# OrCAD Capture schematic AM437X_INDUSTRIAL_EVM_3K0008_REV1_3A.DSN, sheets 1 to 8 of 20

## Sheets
1 Pg15: Motor Sense: size C; title: AM437x Industrial EVM; rev: 1.3A; company: Texas Instruments; note: am437x_industrial_evm_3k0008.dsn; note: ARM MPU BU; note: Final
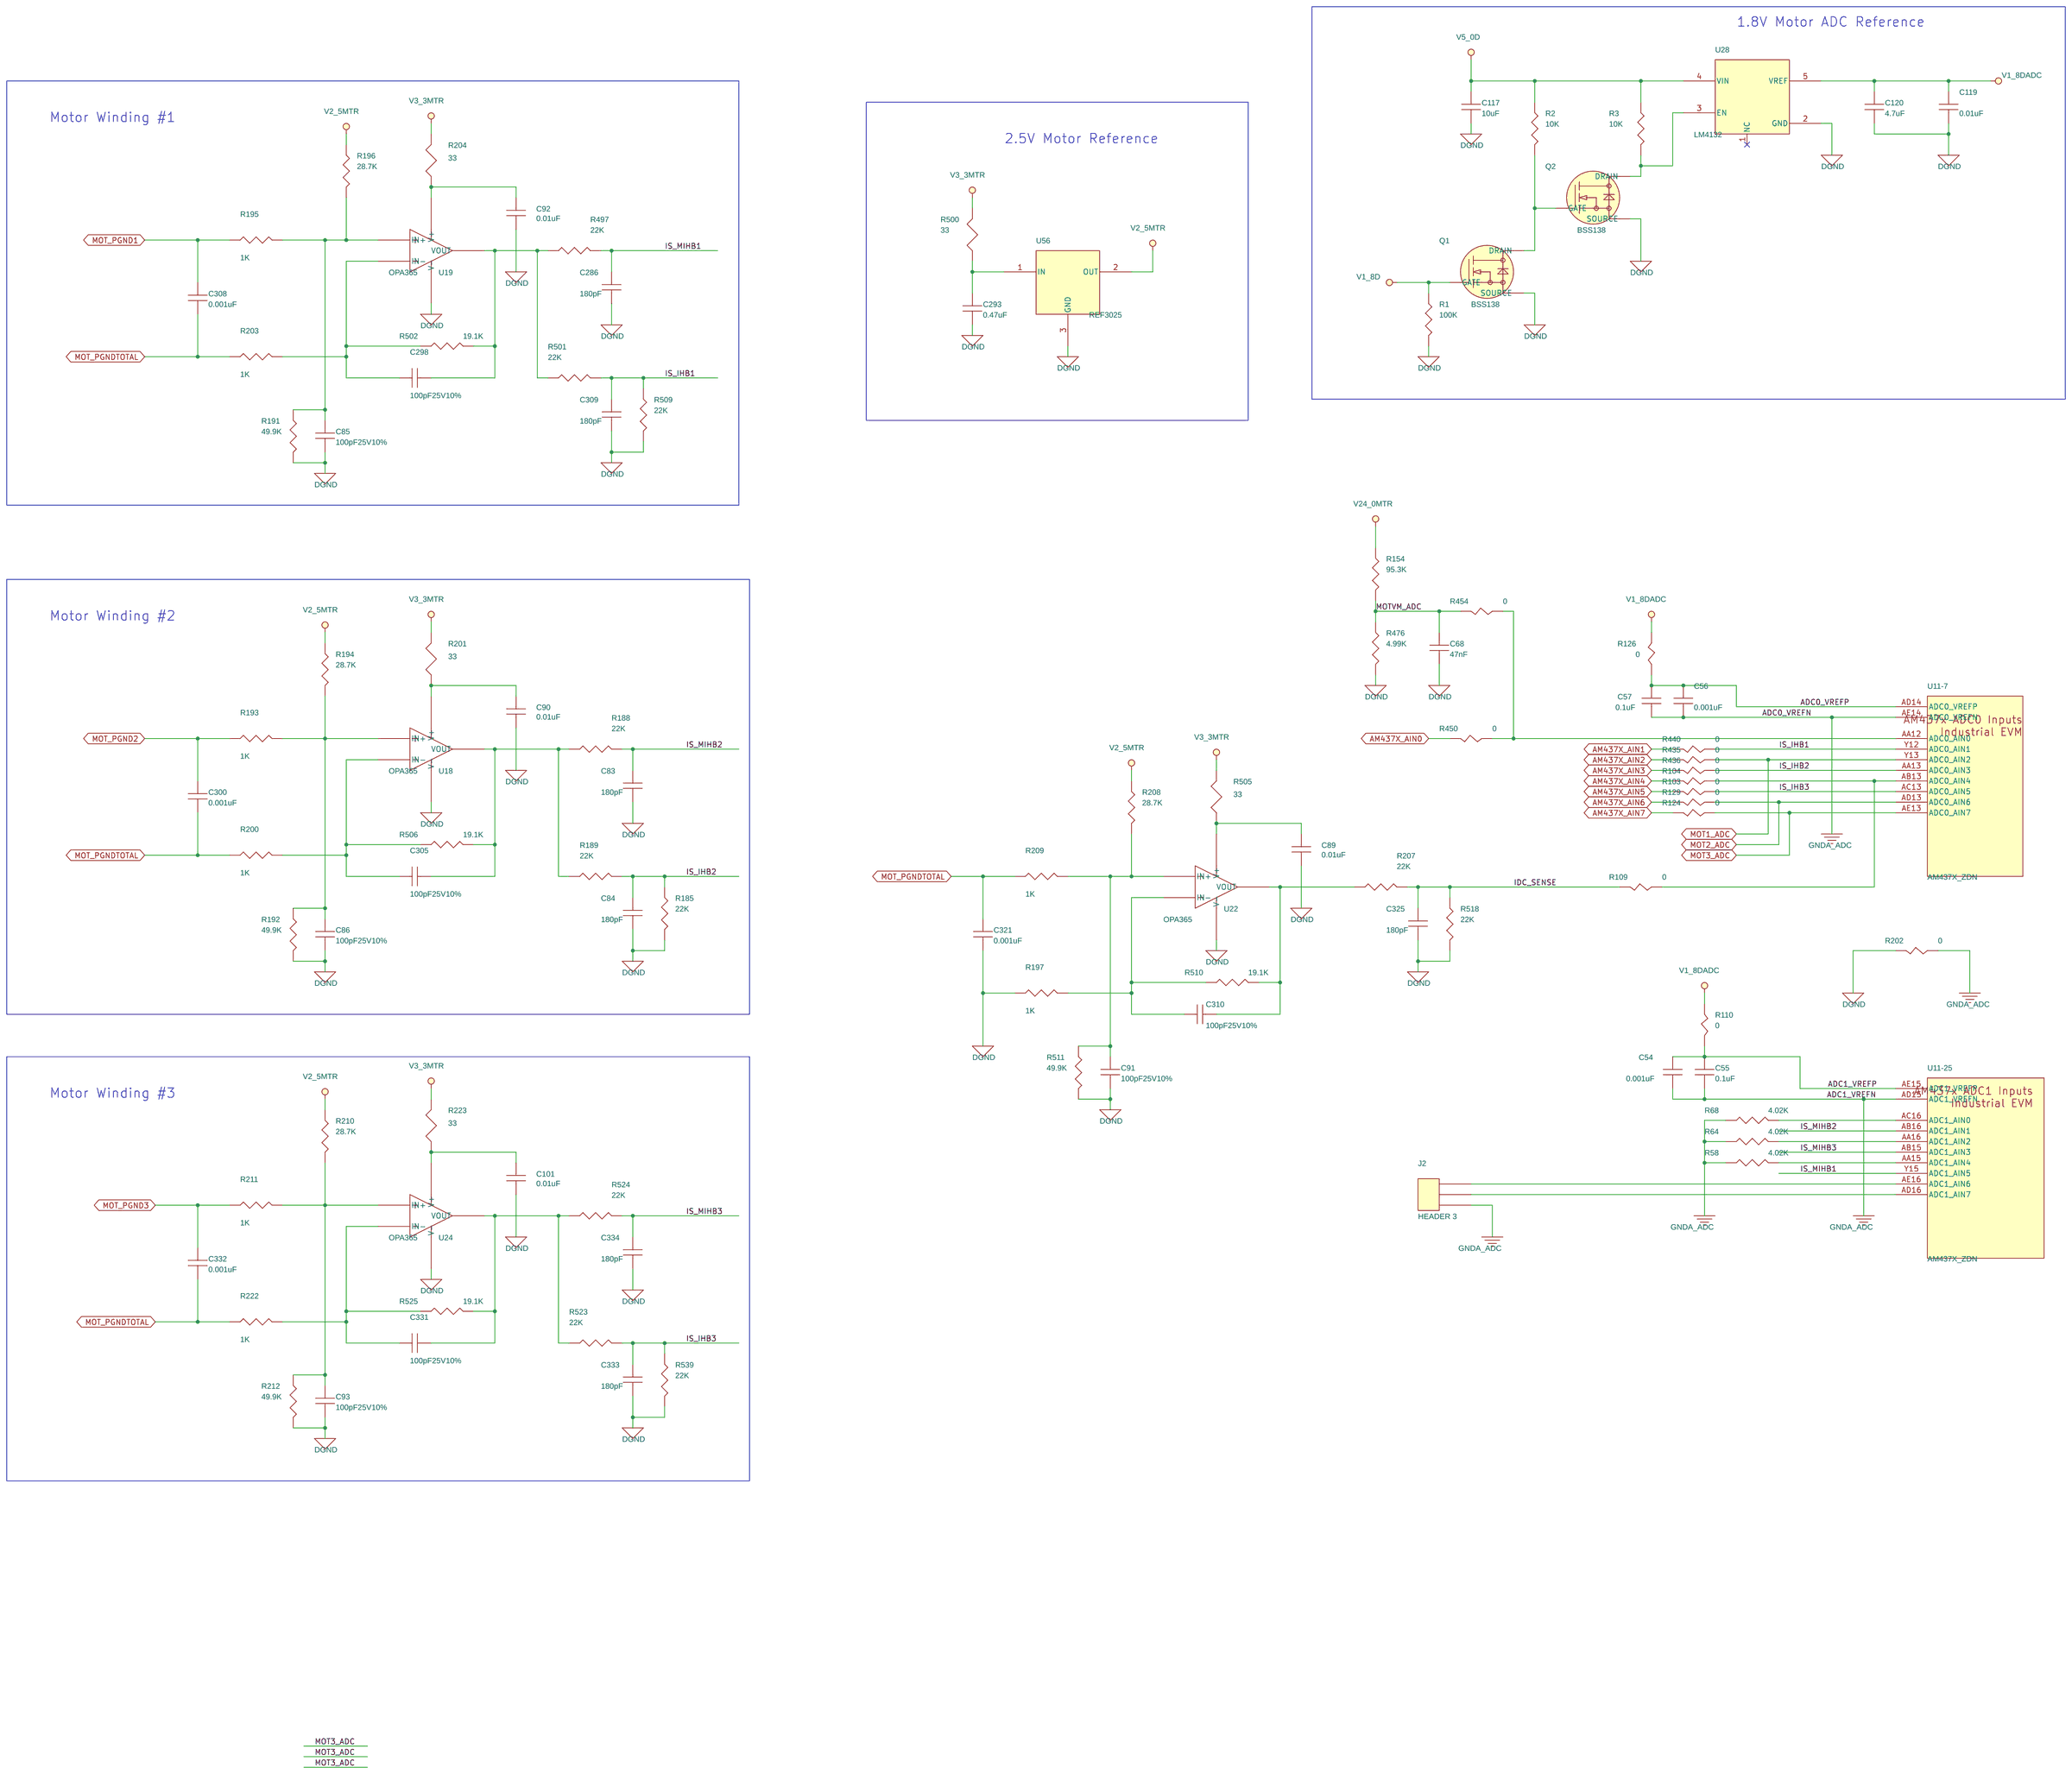
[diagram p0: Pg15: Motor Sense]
2 Pg12: Camera #0: size C
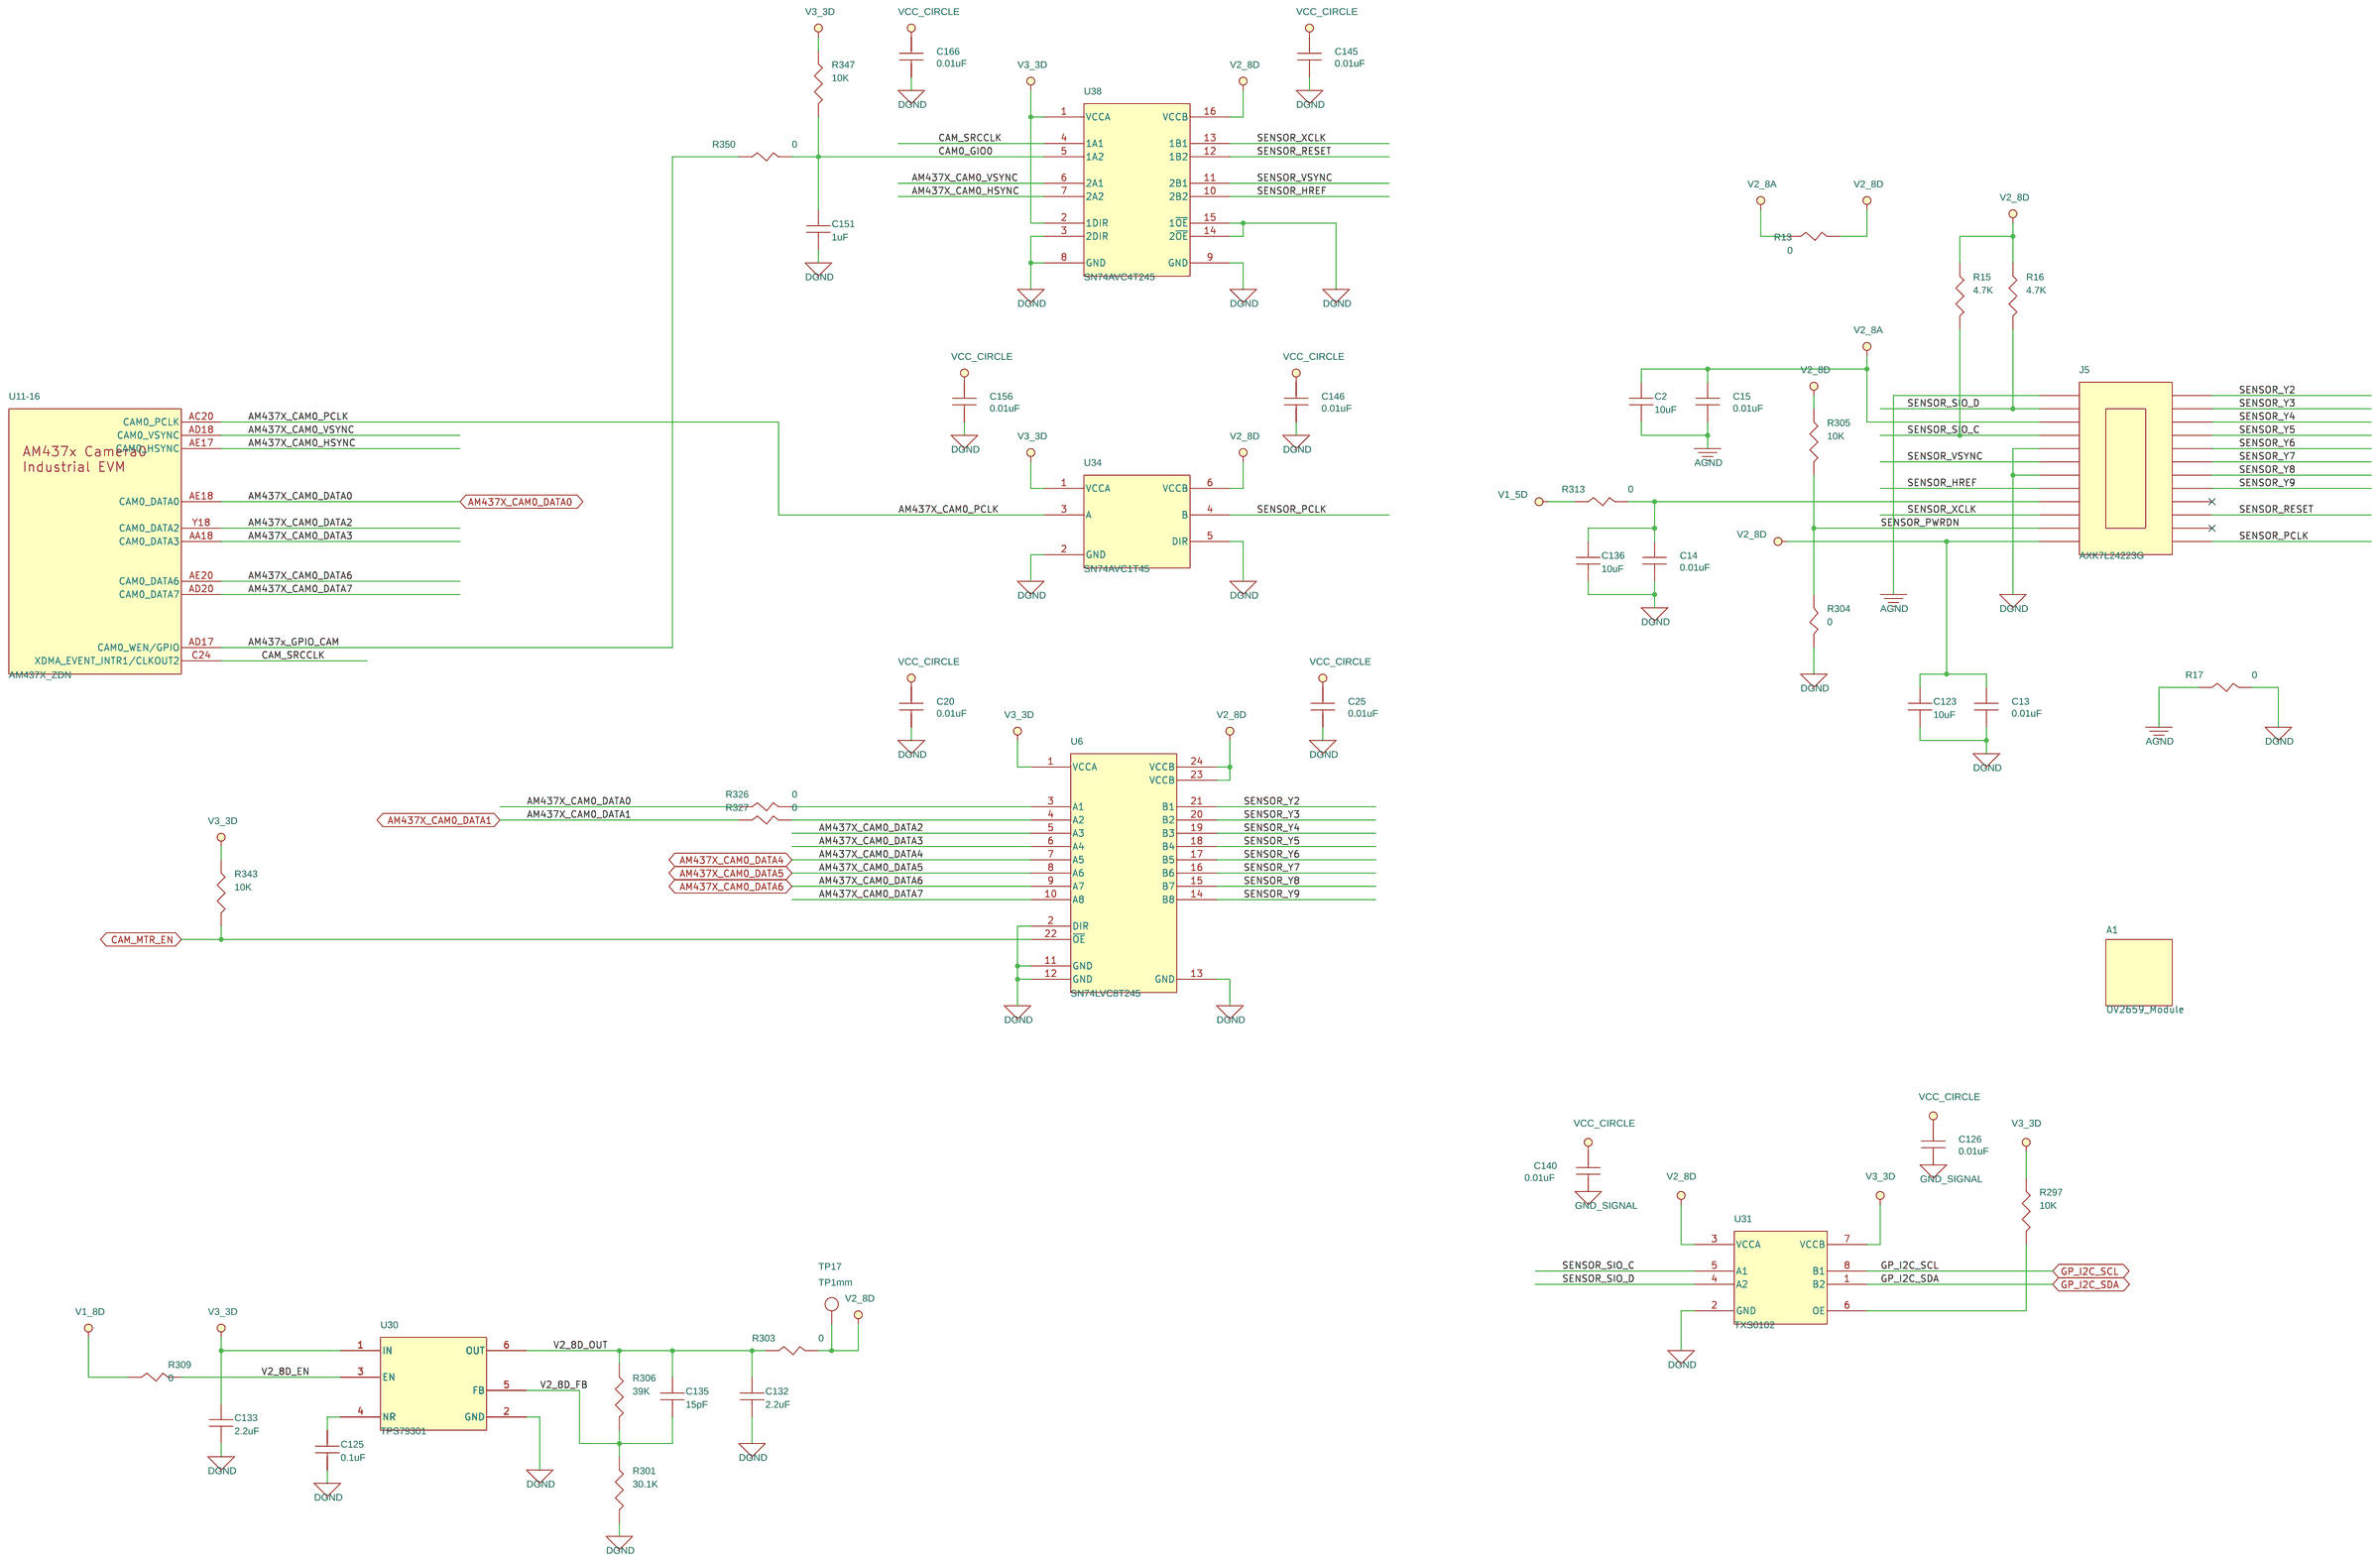
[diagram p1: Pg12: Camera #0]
3 Pg09: EtherCAT: size C
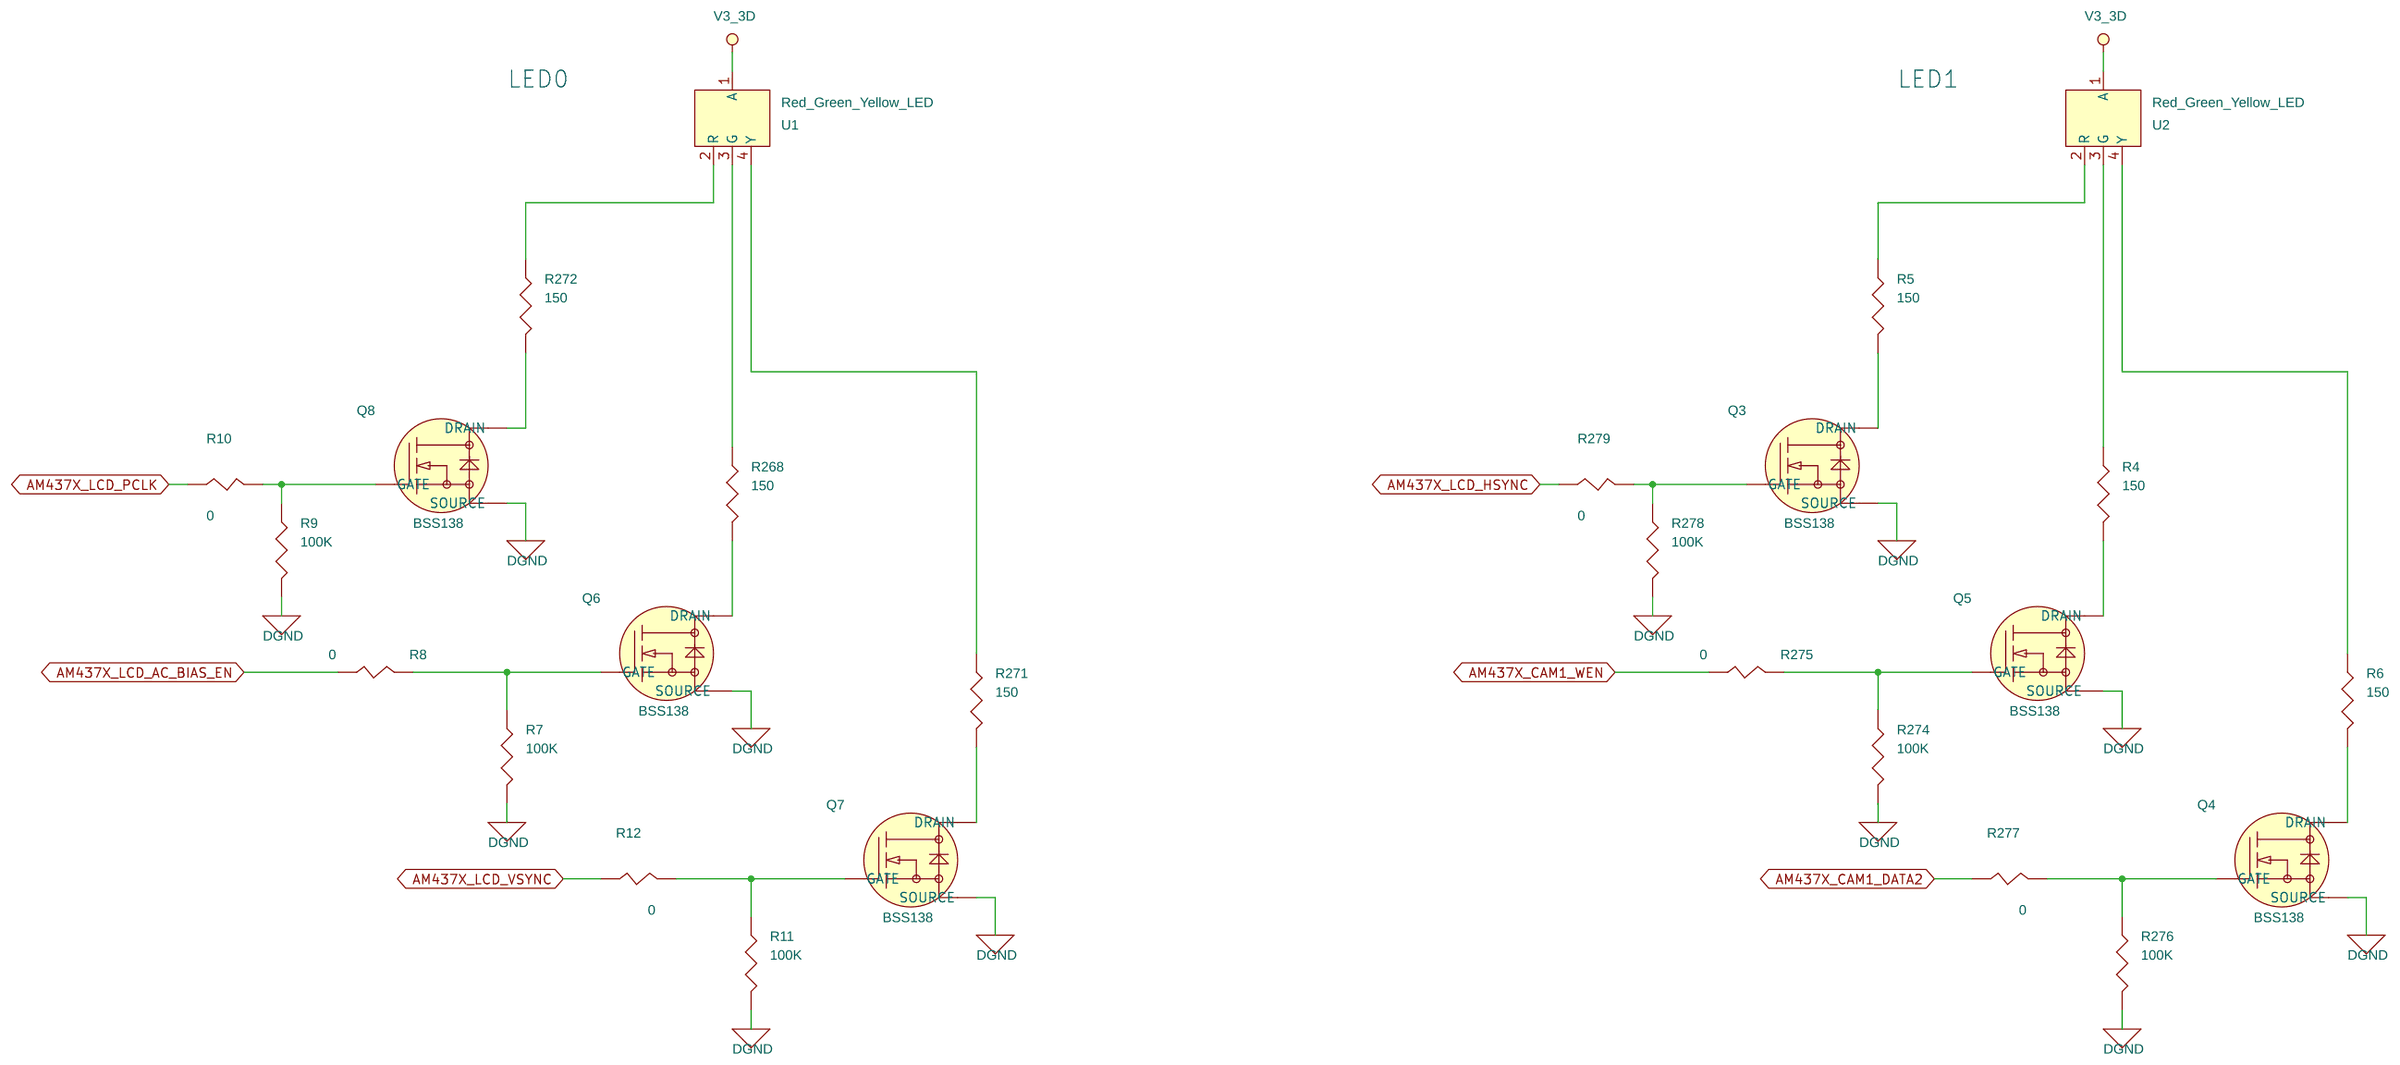
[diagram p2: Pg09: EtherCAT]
4 Pg20: RTC: size C
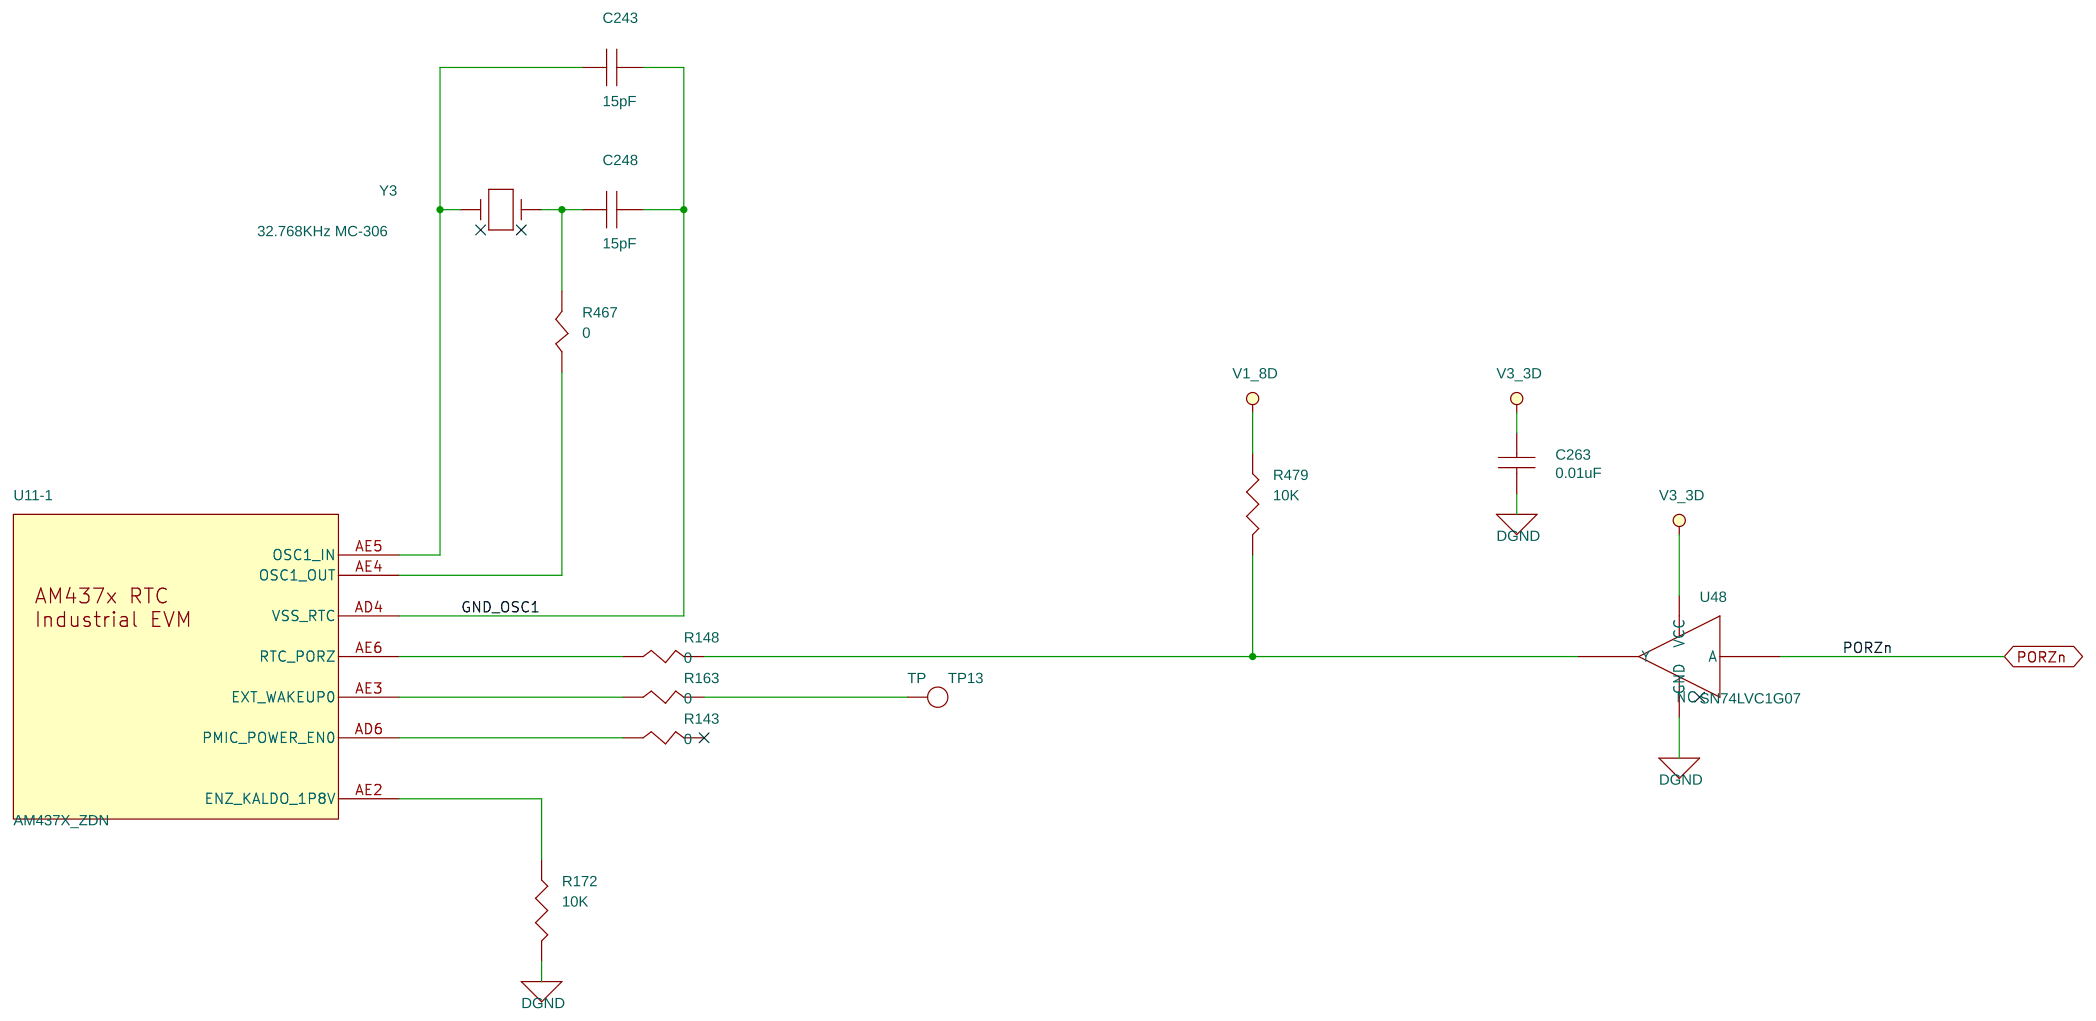
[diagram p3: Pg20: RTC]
5 Pg18: USB JTAG: size C
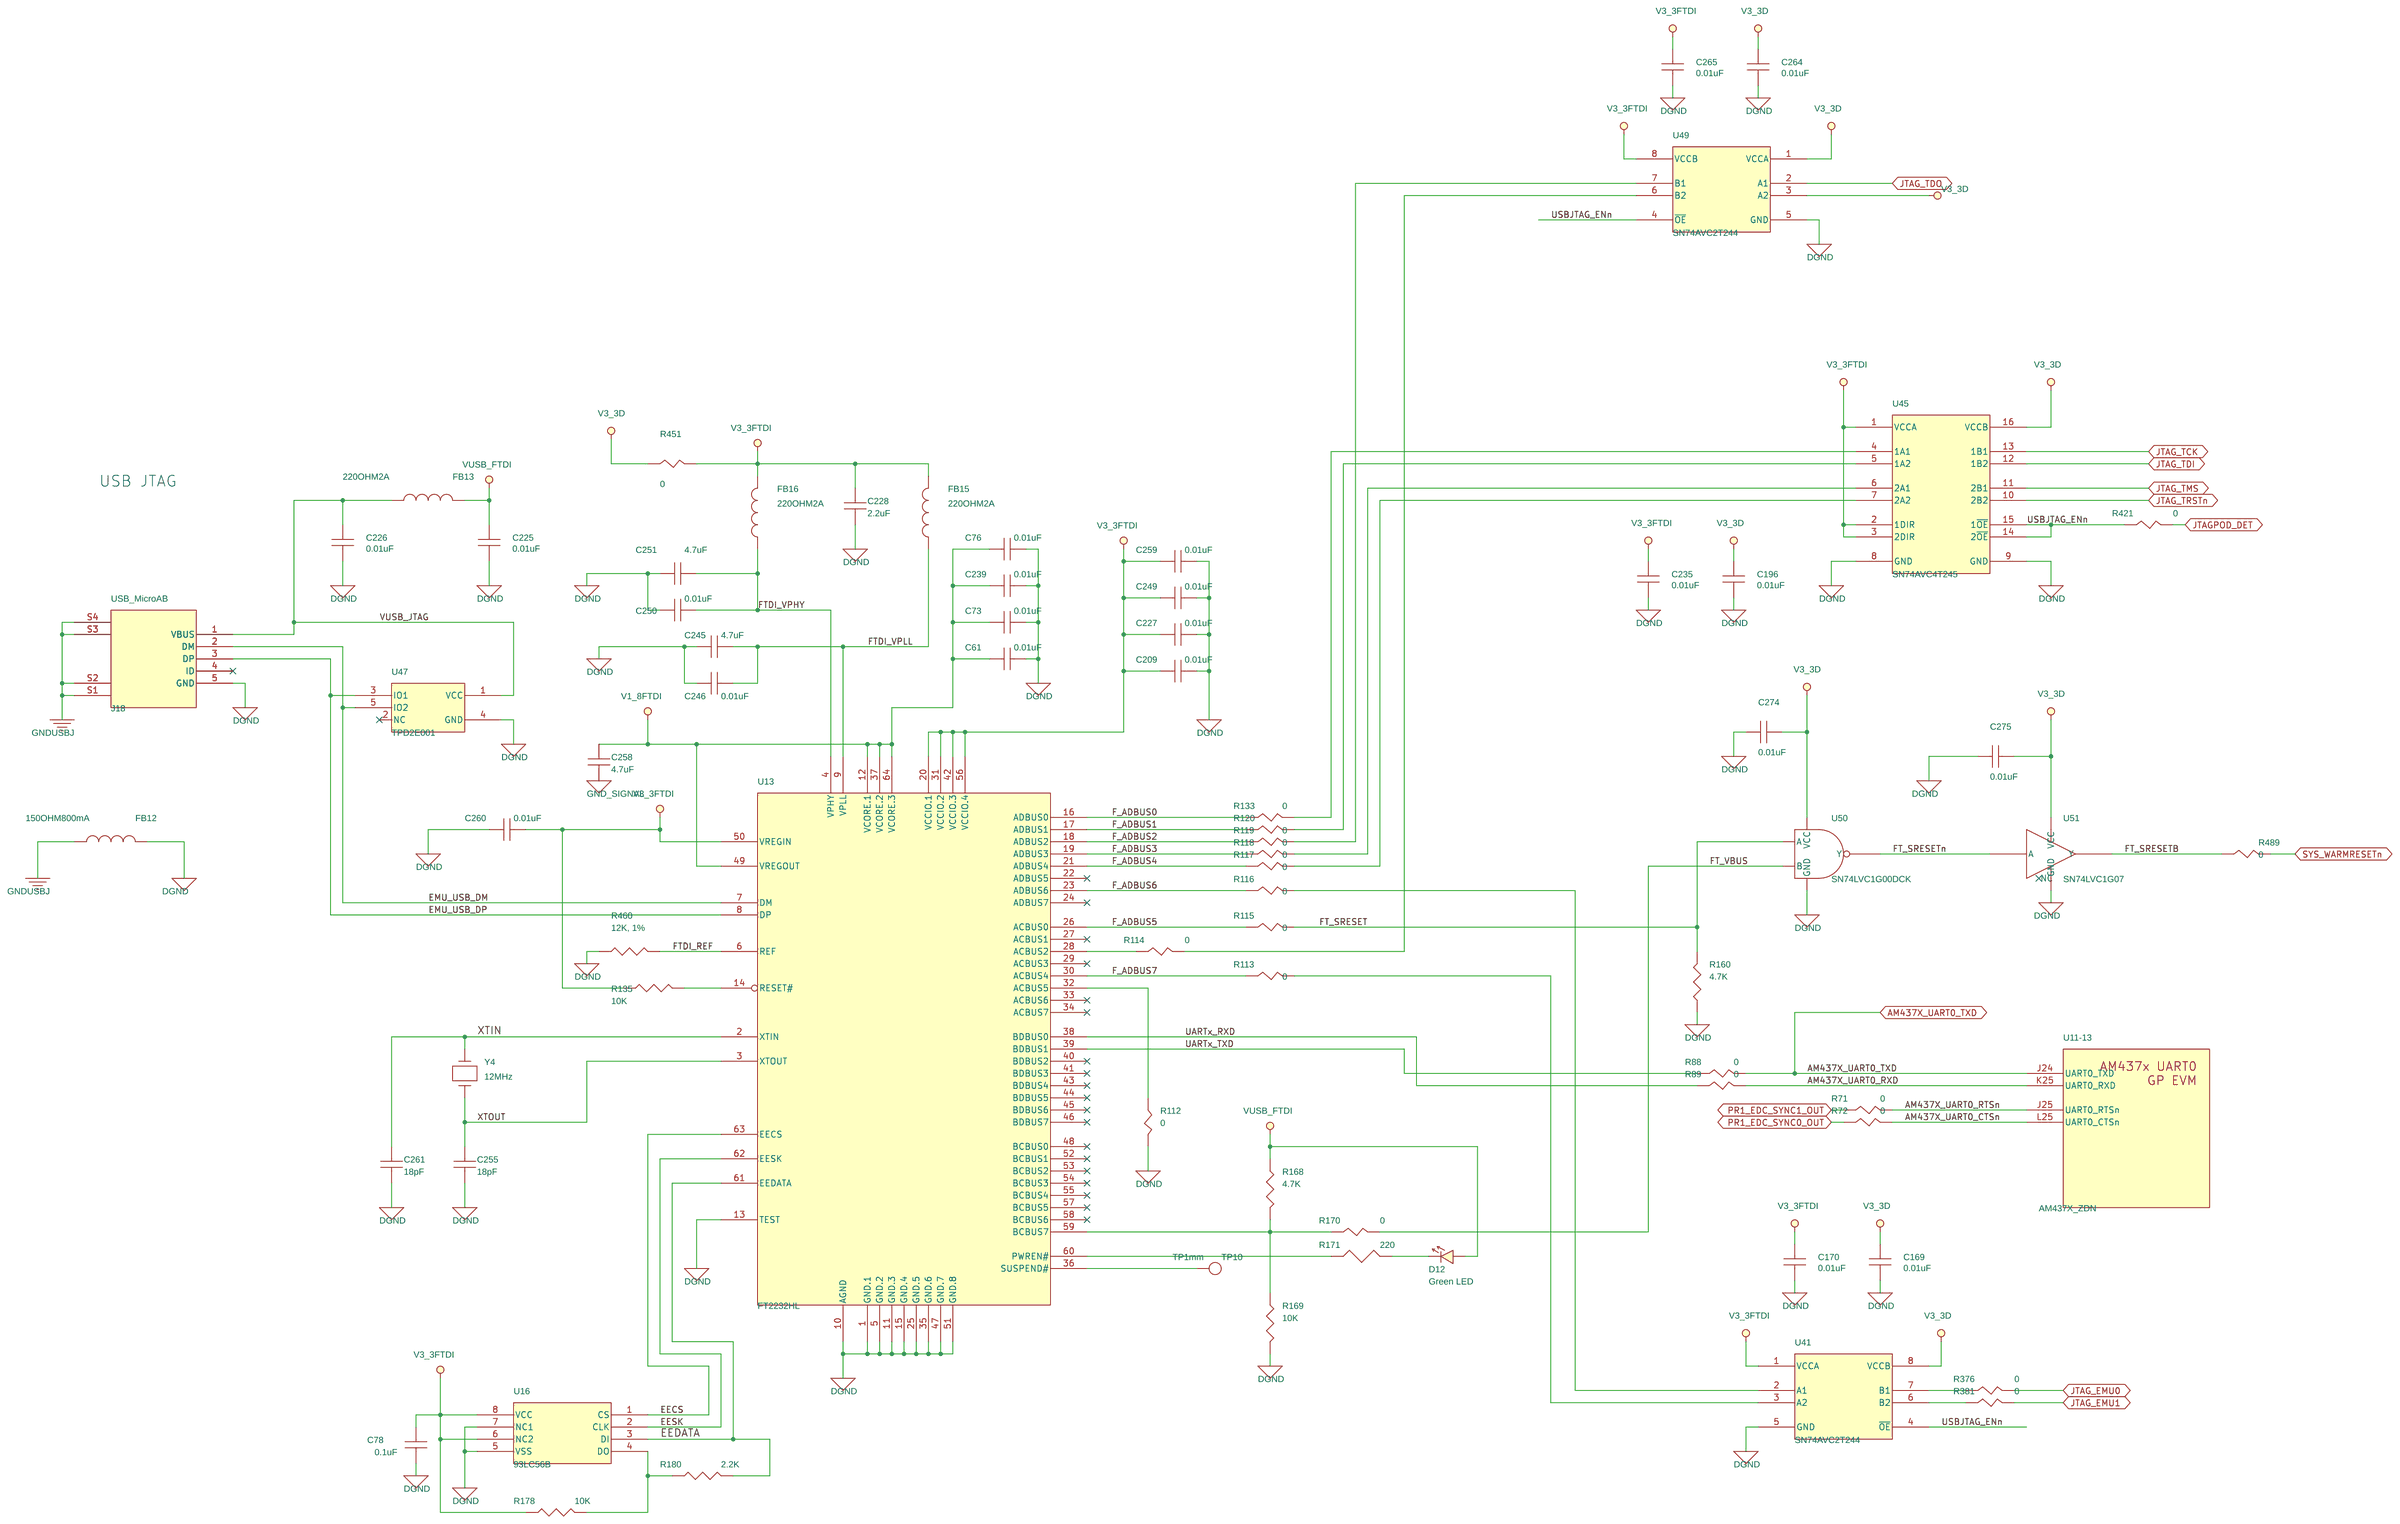
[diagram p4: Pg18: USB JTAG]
6 Pg17: JTAG Debug: size C
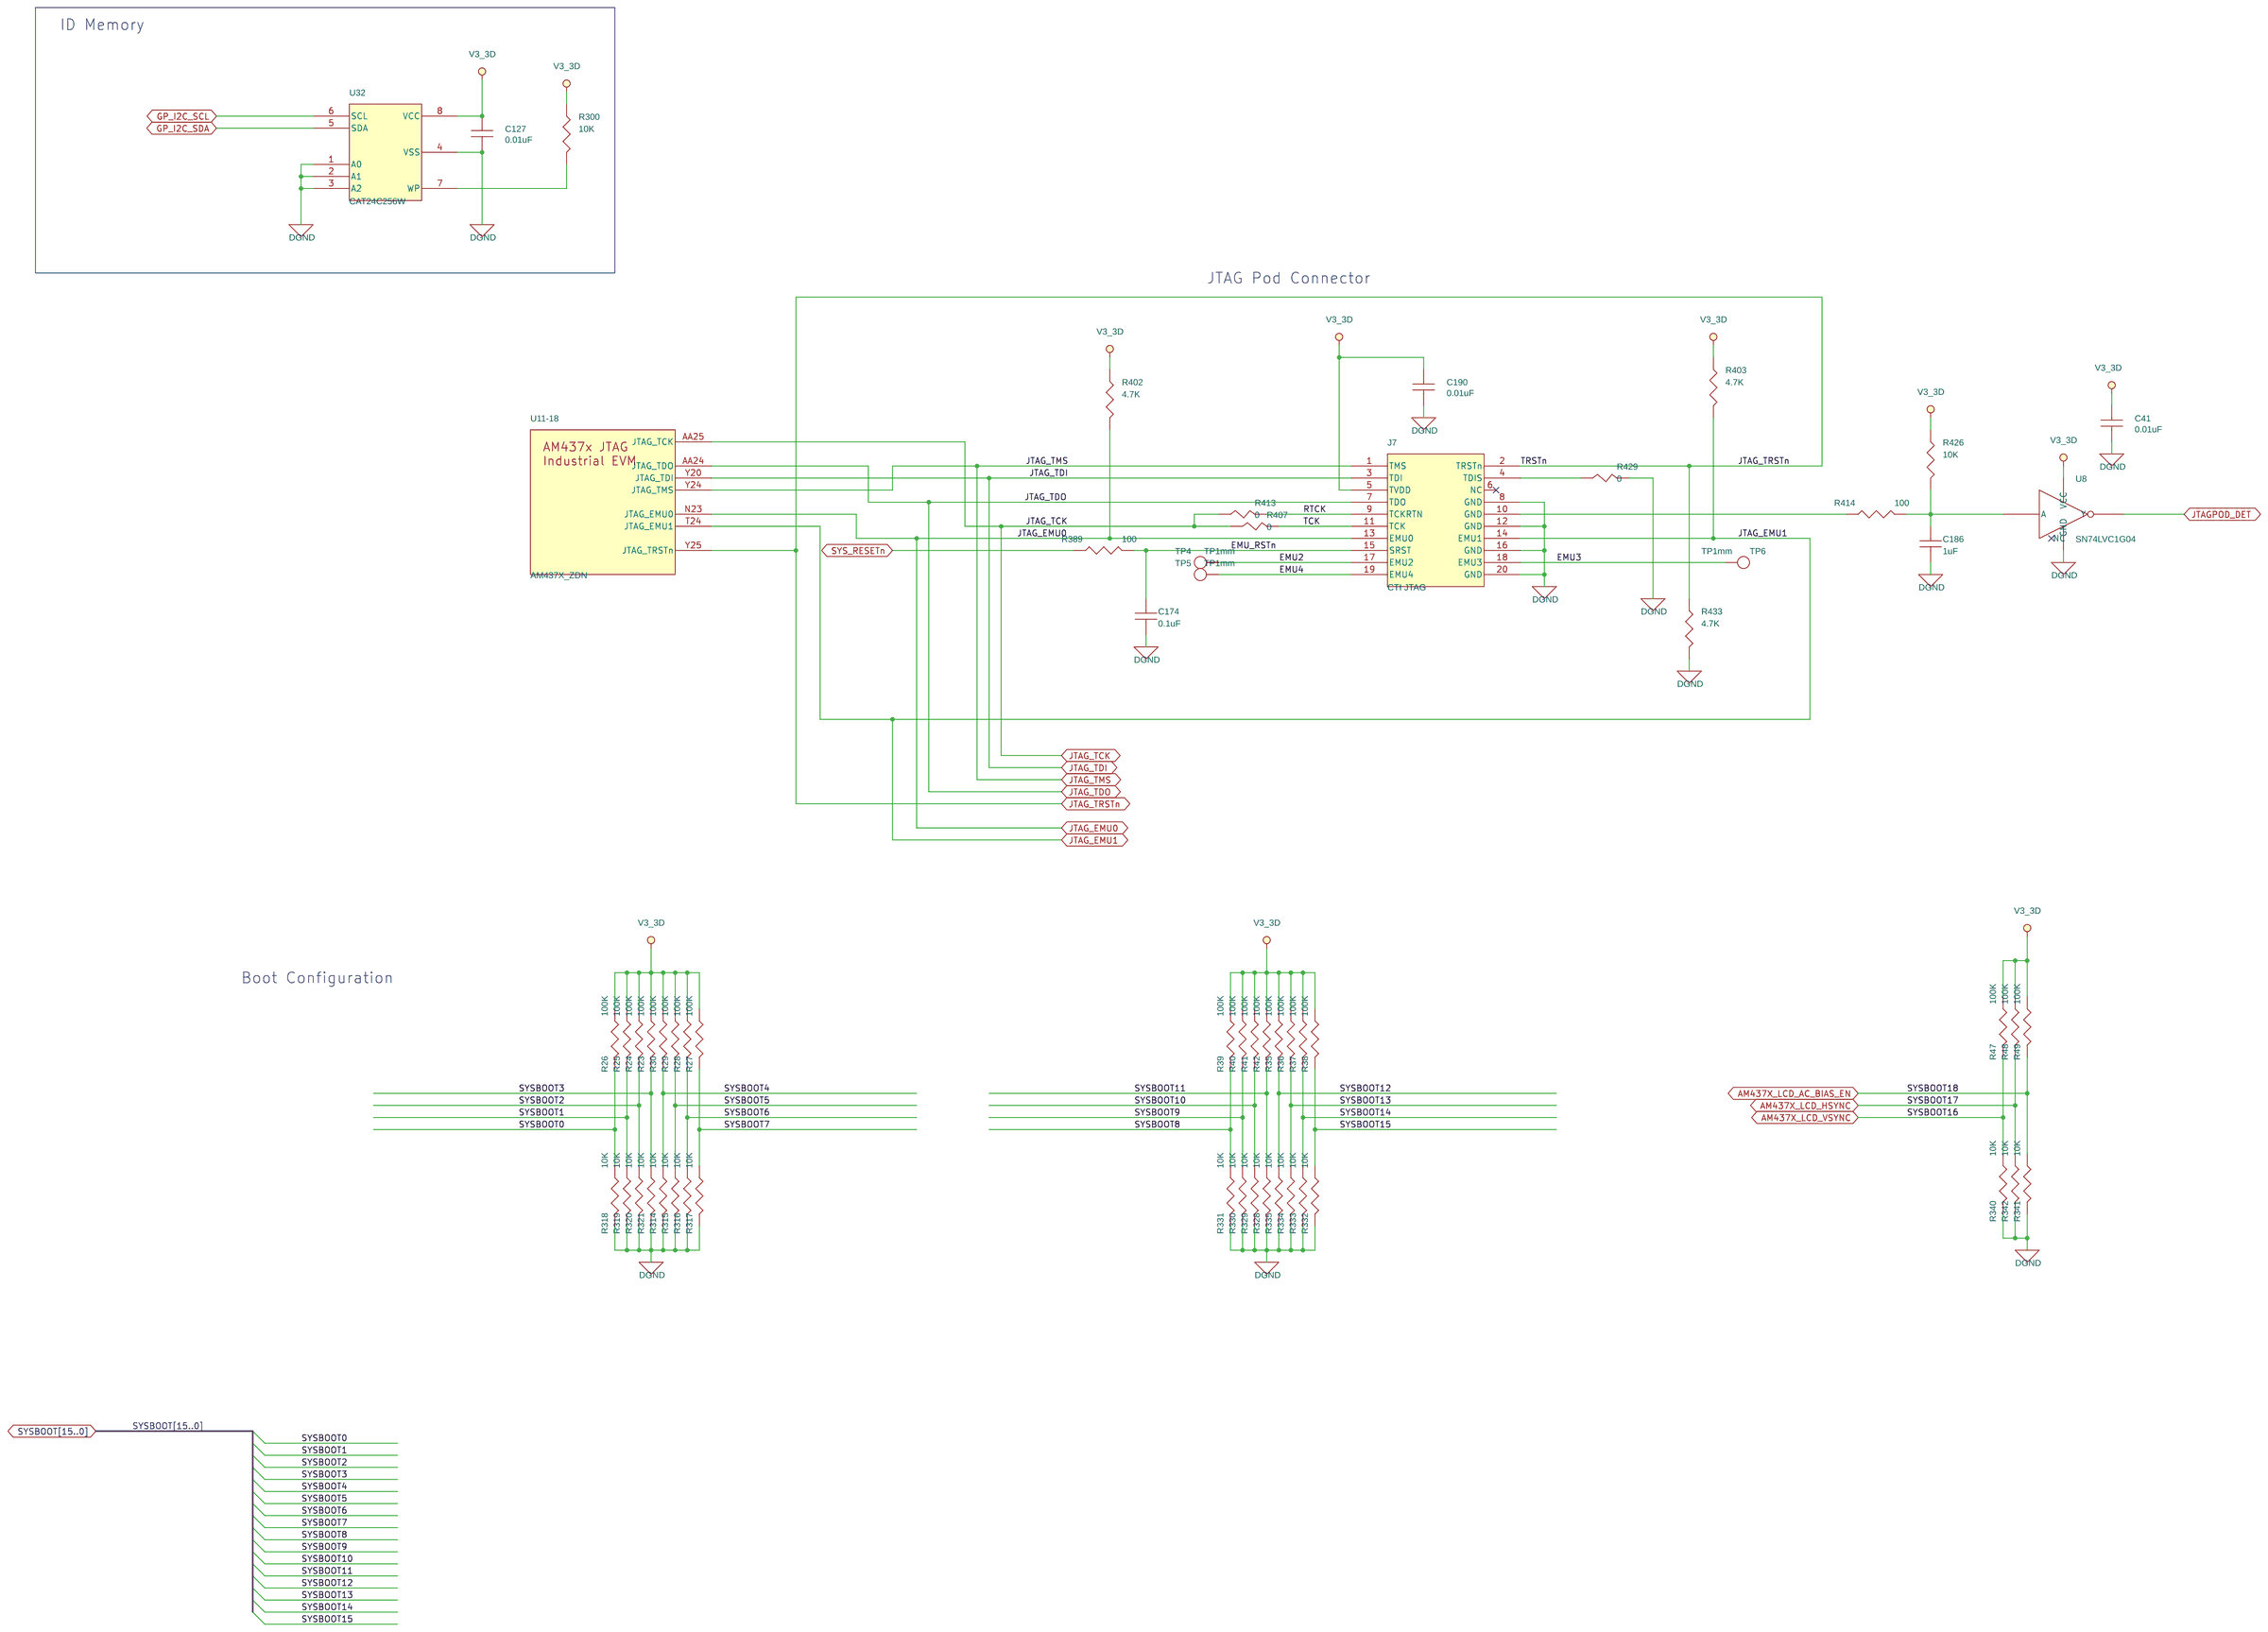
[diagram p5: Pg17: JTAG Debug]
7 Pg01: Title Page
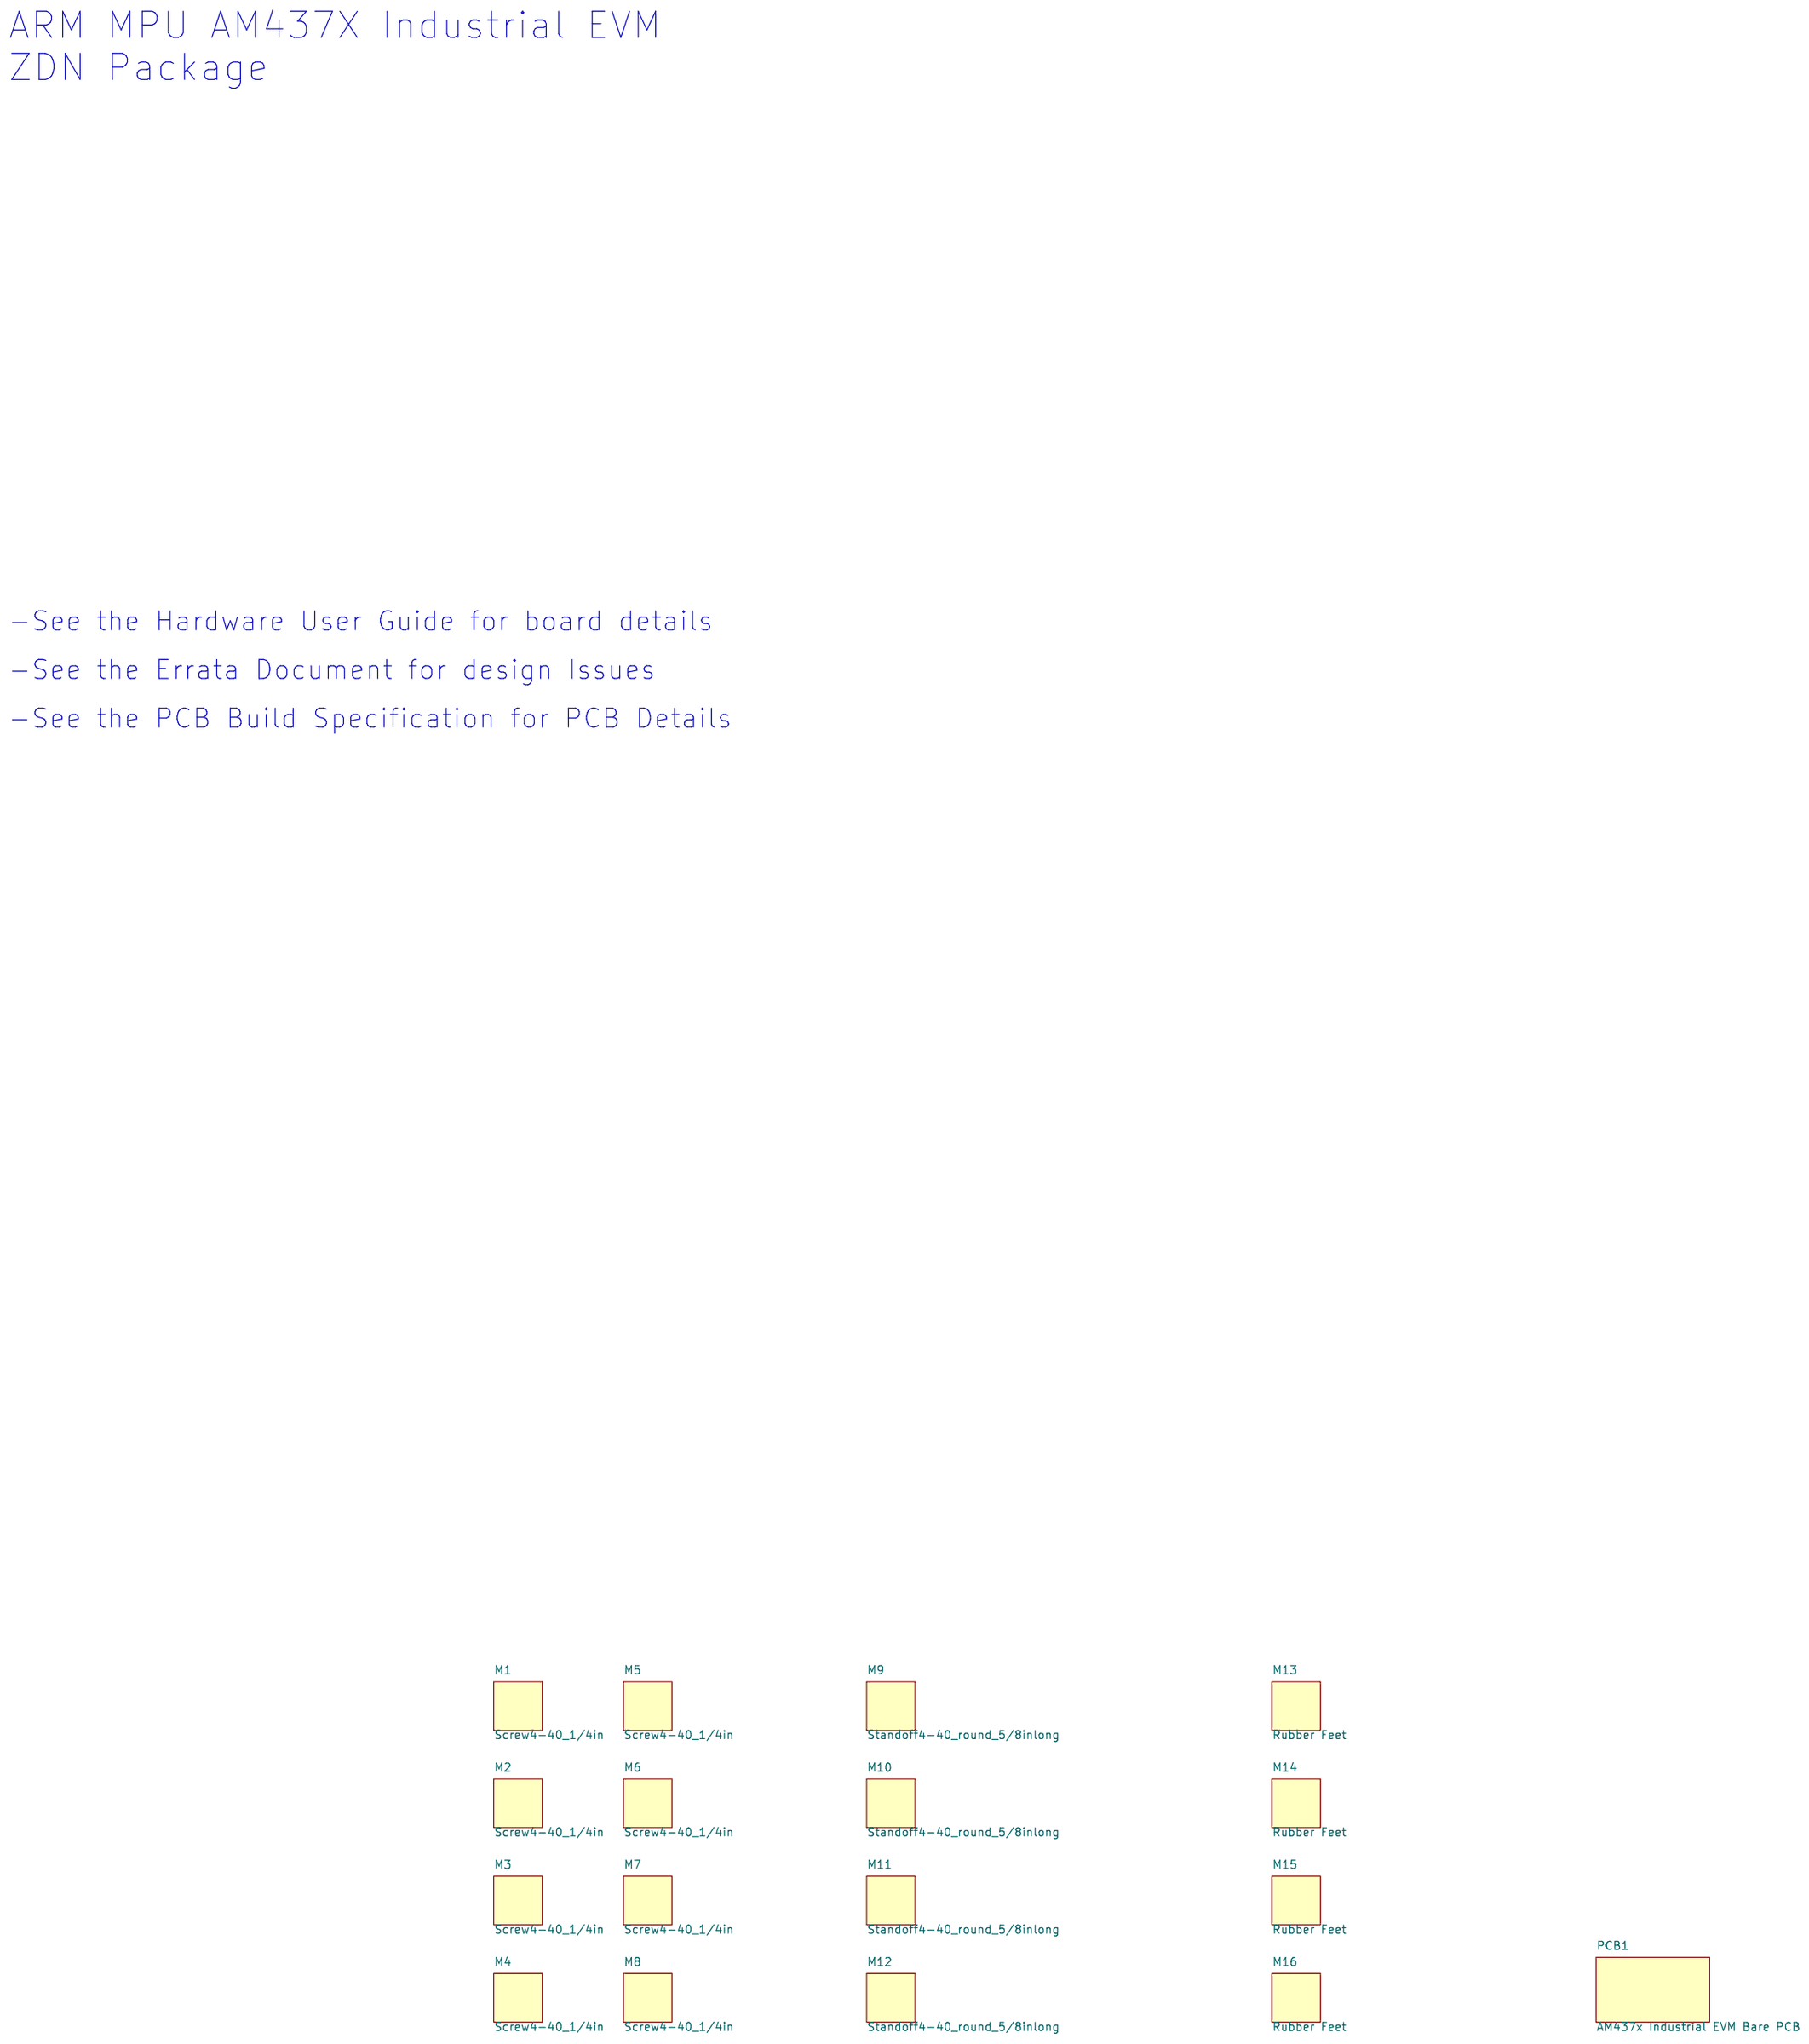
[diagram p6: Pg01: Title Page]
8 Pg06: DDR3 Memory: size C
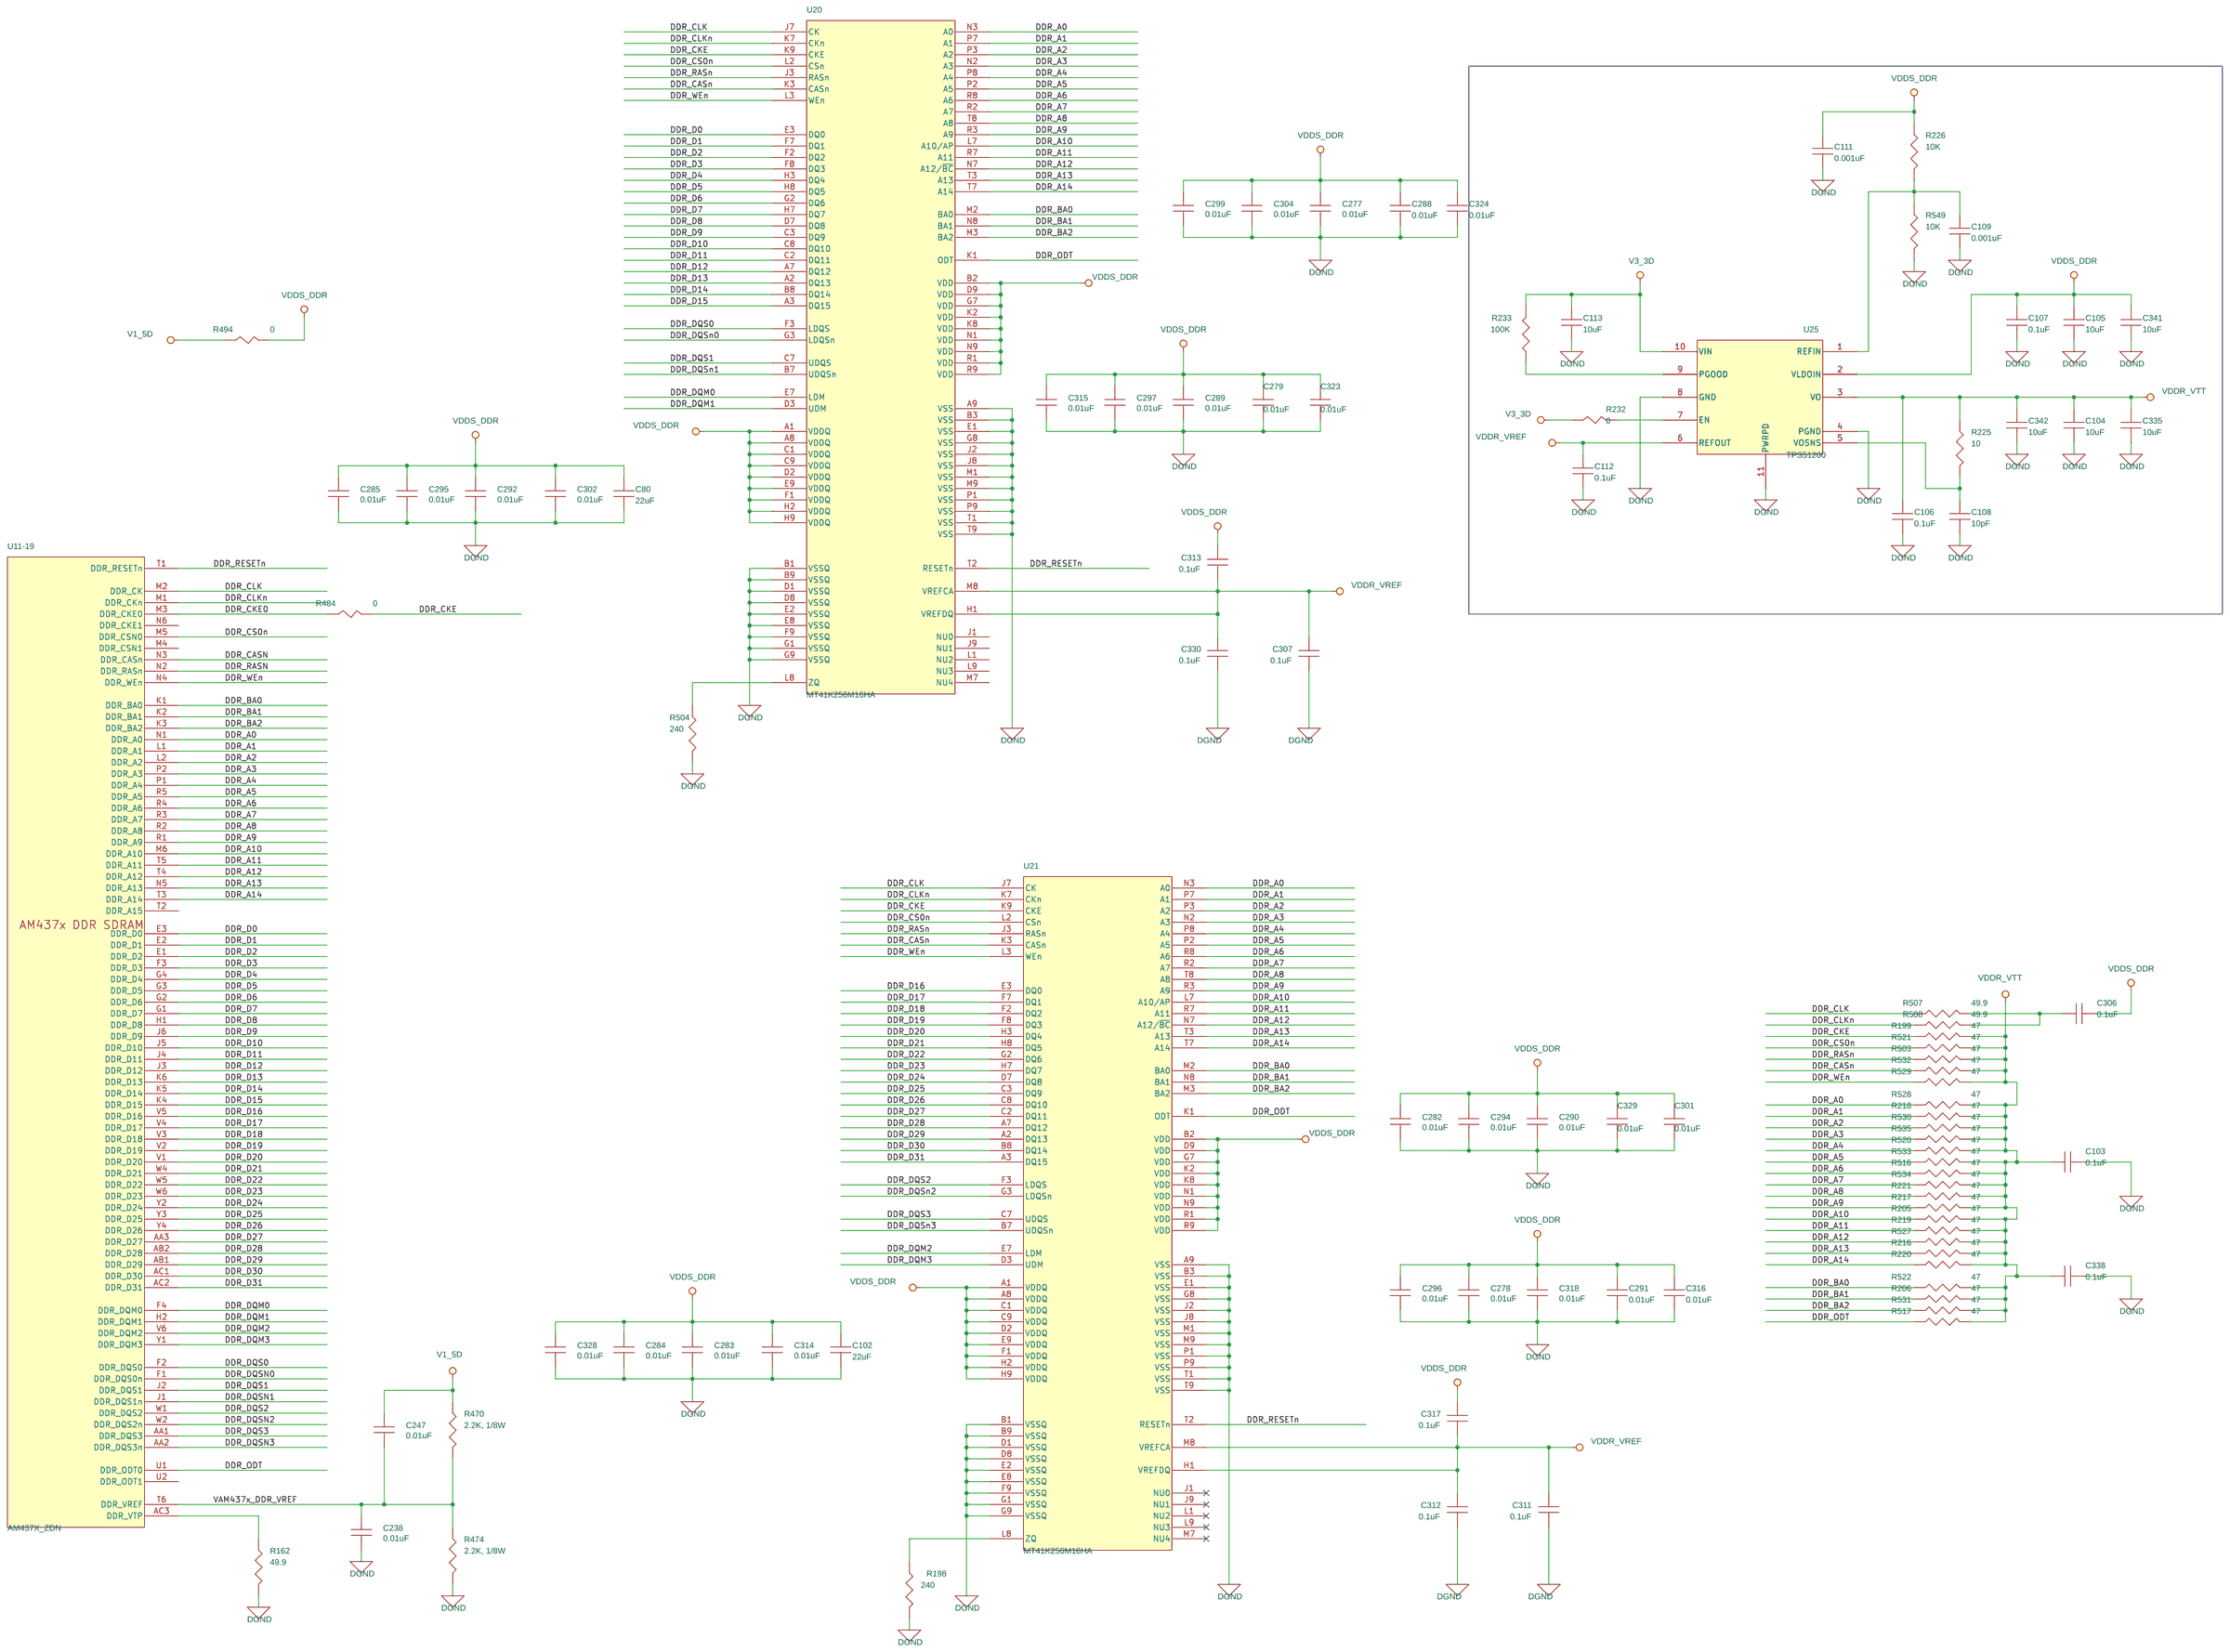
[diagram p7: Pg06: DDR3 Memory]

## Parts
sheet Pg01: Title Page
M1  Screw4-40_1/4in  [DNP]
M2  Screw4-40_1/4in  [DNP]
M3  Screw4-40_1/4in  [DNP]
M4  Screw4-40_1/4in  [DNP]
M5  Screw4-40_1/4in  [DNP]
M6  Screw4-40_1/4in  [DNP]
M7  Screw4-40_1/4in  [DNP]
M8  Screw4-40_1/4in  [DNP]
M9  Standoff4-40_round_5/8inlong  [DNP]
M10  Standoff4-40_round_5/8inlong  [DNP]
M11  Standoff4-40_round_5/8inlong  [DNP]
M12  Standoff4-40_round_5/8inlong  [DNP]
M13  Rubber Feet  [DNP]
M14  Rubber Feet  [DNP]
M15  Rubber Feet  [DNP]
M16  Rubber Feet  [DNP]
PCB1  AM437x Industrial EVM Bare PCB  [DNP]
sheet Pg06: DDR3 Memory
C80  22uF  [SM-7351-CAP-0805]
C102  22uF  [SM-7351-CAP-0805]
C103  0.1uF  [SM-7351-CAP-0402]
C104  10uF  [SM-7351-CAP-0805]
C105  10uF  [SM-7351-CAP-0805]
C106  0.1uF  [SM-7351-CAP-0402]
C107  0.1uF  [SM-7351-CAP-0402]
C108  10pF  [SM-7351-CAP-0402]
C109  0.001uF  [SM-7351-CAP-0402]
C111  0.001uF  [SM-7351-CAP-0402]
C112  0.1uF  [SM-7351-CAP-0402]
C113  10uF  [SM-7351-CAP-0805]
C238  0.01uF  [SM-7351-CAP-0402]
C247  0.01uF  [SM-7351-CAP-0402]
C277  0.01uF  [SM-7351-CAP-0402]
C278  0.01uF  [SM-7351-CAP-0402]
C279  0.01uF  [SM-7351-CAP-0402]
C282  0.01uF  [SM-7351-CAP-0402]
C283  0.01uF  [SM-7351-CAP-0402]
C284  0.01uF  [SM-7351-CAP-0402]
C285  0.01uF  [SM-7351-CAP-0402]
C288  0.01uF  [SM-7351-CAP-0402]
C289  0.01uF  [SM-7351-CAP-0402]
C290  0.01uF  [SM-7351-CAP-0402]
C291  0.01uF  [SM-7351-CAP-0402]
C292  0.01uF  [SM-7351-CAP-0402]
C294  0.01uF  [SM-7351-CAP-0402]
C295  0.01uF  [SM-7351-CAP-0402]
C296  0.01uF  [SM-7351-CAP-0402]
C297  0.01uF  [SM-7351-CAP-0402]
C299  0.01uF  [SM-7351-CAP-0402]
C301  0.01uF  [SM-7351-CAP-0402]
C302  0.01uF  [SM-7351-CAP-0402]
C304  0.01uF  [SM-7351-CAP-0402]
C306  0.1uF  [SM-7351-CAP-0402]
C307  0.1uF  [SM-7351-CAP-0402]
C311  0.1uF  [SM-7351-CAP-0402]
C312  0.1uF  [SM-7351-CAP-0402]
C313  0.1uF  [SM-7351-CAP-0402]
C314  0.01uF  [SM-7351-CAP-0402]
C315  0.01uF  [SM-7351-CAP-0402]
C316  0.01uF  [SM-7351-CAP-0402]
C317  0.1uF  [SM-7351-CAP-0402]
C318  0.01uF  [SM-7351-CAP-0402]
C323  0.01uF  [SM-7351-CAP-0402]
C324  0.01uF  [SM-7351-CAP-0402]
C328  0.01uF  [SM-7351-CAP-0402]
C329  0.01uF  [SM-7351-CAP-0402]
C330  0.1uF  [SM-7351-CAP-0402]
C335  10uF  [SM-7351-CAP-0805]
C338  0.1uF  [SM-7351-CAP-0402]
C341  10uF  [SM-7351-CAP-0805]
C342  10uF  [SM-7351-CAP-0805]
R162  49.9  [SM-7351-RES-0402]
R198  240  [sm-7351-res-0402]
R199  47  [SM-7351-RES-0402]
R205  47  [SM-7351-RES-0402]
R206  47  [SM-7351-RES-0402]
R216  47  [SM-7351-RES-0402]
R217  47  [SM-7351-RES-0402]
R218  47  [SM-7351-RES-0402]
R219  47  [SM-7351-RES-0402]
R220  47  [SM-7351-RES-0402]
R221  47  [SM-7351-RES-0402]
R225  10  [SM-7351-RES-0402]
R226  10K  [SM-7351-RES-0402]
R232  0  [SM-7351-RES-0402]
R233  100K  [SM-7351-RES-0402]
R470  2.2K, 1/8W  [SM-7351-RES-0402]
R474  2.2K, 1/8W  [SM-7351-RES-0402]
R484  0  [SM-7351-RES-0402]
R494  0  [SM-7351-RES-0402]
R503  47  [SM-7351-RES-0402]
R504  240  [sm-7351-res-0402]
R507  49.9  [SM-7351-RES-0402]
R508  49.9  [SM-7351-RES-0402]
R516  47  [SM-7351-RES-0402]
R517  47  [SM-7351-RES-0402]
R520  47  [SM-7351-RES-0402]
R521  47  [SM-7351-RES-0402]
R522  47  [SM-7351-RES-0402]
R527  47  [SM-7351-RES-0402]
R528  47  [SM-7351-RES-0402]
R529  47  [SM-7351-RES-0402]
R530  47  [SM-7351-RES-0402]
R531  47  [SM-7351-RES-0402]
R532  47  [SM-7351-RES-0402]
R533  47  [SM-7351-RES-0402]
R534  47  [SM-7351-RES-0402]
R535  47  [SM-7351-RES-0402]
R549  10K  [SM-7351-RES-0402]
U20  MT41K256M16HA  [bga9x14-96]
U21  MT41K256M16HA  [bga9x14-96]
U25  TPS51200  [drcpso_10pin]
sheet Pg09: EtherCAT
Q3  BSS138  [SOT23-3]
Q4  BSS138  [SOT23-3]
Q5  BSS138  [SOT23-3]
Q6  BSS138  [SOT23-3]
Q7  BSS138  [SOT23-3]
Q8  BSS138  [SOT23-3]
R4  150  [SM-7351-RES-0402]
R5  150  [SM-7351-RES-0402]
R6  150  [SM-7351-RES-0402]
R7  100K  [SM-7351-RES-0402]
R8  0  [SM-7351-RES-0402]
R9  100K  [SM-7351-RES-0402]
R10  0  [SM-7351-RES-0402]
R11  100K  [SM-7351-RES-0402]
R12  0  [SM-7351-RES-0402]
R268  150  [SM-7351-RES-0402]
R271  150  [SM-7351-RES-0402]
R272  150  [SM-7351-RES-0402]
R274  100K  [SM-7351-RES-0402]
R275  0  [SM-7351-RES-0402]
R276  100K  [SM-7351-RES-0402]
R277  0  [SM-7351-RES-0402]
R278  100K  [SM-7351-RES-0402]
R279  0  [SM-7351-RES-0402]
U1  Red_Green_Yellow_LED  [LED-SM1210]
U2  Red_Green_Yellow_LED  [LED-SM1210]
sheet Pg12: Camera #0
A1  OV2659_Module  [DNP]
C2  10uF  [SM-7351-CAP-0805]
C13  0.01uF  [SM-7351-CAP-0402]
C14  0.01uF  [SM-7351-CAP-0402]
C15  0.01uF  [SM-7351-CAP-0402]
C20  0.01uF  [SM-7351-CAP-0402]
C25  0.01uF  [SM-7351-CAP-0402]
C123  10uF  [SM-7351-CAP-0805]
C125  0.1uF  [SM-7351-CAP-0402]
C126  0.01uF  [SM-7351-CAP-0402]
C132  2.2uF  [SM-7351-CAP-0603]
C133  2.2uF  [SM-7351-CAP-0603]
C135  15pF  [SM-7351-CAP-0402]
C136  10uF  [SM-7351-CAP-0805]
C140  0.01uF  [SM-7351-CAP-0402]
C145  0.01uF  [SM-7351-CAP-0402]
C146  0.01uF  [SM-7351-CAP-0402]
C151  1uF  [SM-7351-CAP-0402]
C156  0.01uF  [SM-7351-CAP-0402]
C166  0.01uF  [SM-7351-CAP-0402]
J5  AXK7L24223G  [SCKAXK7L24]
R13  0  [SM-7351-RES-0603]
R15  4.7K  [SM-7351-RES-0402]
R16  4.7K  [SM-7351-RES-0402]
R17  0  [SM-7351-RES-0603]
R297  10K  [SM-7351-RES-0402]
R301  30.1K  [SM-7351-RES-0402]
R303  0  [SM-7351-RES-0603]
R304  0  [SM-7351-RES-0402]
R305  10K  [SM-7351-RES-0402]
R306  39K  [SM-7351-RES-0402]
R309  0  [SM-7351-RES-0402]
R313  0  [SM-7351-RES-0603]
R326  0  [SM-7351-RES-0603]
R327  0  [SM-7351-RES-0603]
R343  10K  [SM-7351-RES-0402]
R347  10K  [SM-7351-RES-0402]
R350  0  [SM-7351-RES-0402]
TP17  TP1mm  [tp_smd1mmcircle]
U6  SN74LVC8T245  [TSSOP8X4-24-47M]
U30  TPS79301  [U_6_DBV]
U31  TXS0102  [dct8]
U34  SN74AVC1T45  [smdsc70-6]
U38  SN74AVC4T245  [U_16_PW]
sheet Pg15: Motor Sense
C54  0.001uF  [SM-7351-CAP-0402]
C55  0.1uF  [SM-7351-CAP-0402]
C56  0.001uF  [SM-7351-CAP-0402]
C57  0.1uF  [SM-7351-CAP-0402]
C68  47nF  [SM-7351-CAP-0402]
C83  180pF  [SM-7351-CAP-0402]
C84  180pF  [SM-7351-CAP-0402]
C85  100pF25V10%  [SM-7351-CAP-0402]
C86  100pF25V10%  [SM-7351-CAP-0402]
C89  0.01uF  [SM-7351-CAP-0402]
C90  0.01uF  [SM-7351-CAP-0402]
C91  100pF25V10%  [SM-7351-CAP-0402]
C92  0.01uF  [SM-7351-CAP-0402]
C93  100pF25V10%  [SM-7351-CAP-0402]
C101  0.01uF  [SM-7351-CAP-0402]
C117  10uF  [SM-7351-CAP-0805]
C119  0.01uF  [SM-7351-CAP-0402]
C120  4.7uF  [SM-7351-CAP-0603]
C286  180pF  [SM-7351-CAP-0402]
C293  0.47uF  [SM-7351-CAP-0402]
C298  100pF25V10%  [SM-7351-CAP-0402]
C300  0.001uF  [SM-7351-CAP-0402]
C305  100pF25V10%  [SM-7351-CAP-0402]
C308  0.001uF  [SM-7351-CAP-0402]
C309  180pF  [SM-7351-CAP-0402]
C310  100pF25V10%  [SM-7351-CAP-0402]
C321  0.001uF  [SM-7351-CAP-0402]
C325  180pF  [SM-7351-CAP-0402]
C331  100pF25V10%  [SM-7351-CAP-0402]
C332  0.001uF  [SM-7351-CAP-0402]
C333  180pF  [SM-7351-CAP-0402]
C334  180pF  [SM-7351-CAP-0402]
J2  HEADER 3  [header_3x1]
Q1  BSS138  [SOT23-3]
Q2  BSS138  [SOT23-3]
R1  100K  [SM-7351-RES-0402]
R2  10K  [SM-7351-RES-0402]
R3  10K  [SM-7351-RES-0402]
R58  4.02K  [SM-7351-RES-0402]
R64  4.02K  [SM-7351-RES-0402]
R68  4.02K  [SM-7351-RES-0402]
R103  0  [SM-7351-RES-0402]
R104  0  [SM-7351-RES-0402]
R109  0  [SM-7351-RES-0402]
R110  0  [SM-7351-RES-0402]
R124  0  [SM-7351-RES-0402]
R126  0  [SM-7351-RES-0402]
R129  0  [SM-7351-RES-0402]
R154  95.3K  [SM-7351-RES-0402]
R185  22K  [SM-7351-RES-0402]
R188  22K  [SM-7351-RES-0402]
R189  22K  [SM-7351-RES-0402]
R191  49.9K  [SM-7351-RES-0402]
R192  49.9K  [SM-7351-RES-0402]
R193  1K  [SM-7351-RES-0402]
R194  28.7K  [SM-7351-RES-0402]
R195  1K  [SM-7351-RES-0402]
R196  28.7K  [SM-7351-RES-0402]
R197  1K  [SM-7351-RES-0402]
R200  1K  [SM-7351-RES-0402]
R201  33  [SM-7351-RES-0402]
R202  0  [SM-7351-RES-0402]
R203  1K  [SM-7351-RES-0402]
R204  33  [SM-7351-RES-0402]
R207  22K  [SM-7351-RES-0402]
R208  28.7K  [SM-7351-RES-0402]
R209  1K  [SM-7351-RES-0402]
R210  28.7K  [SM-7351-RES-0402]
R211  1K  [SM-7351-RES-0402]
R212  49.9K  [SM-7351-RES-0402]
R222  1K  [SM-7351-RES-0402]
R223  33  [SM-7351-RES-0402]
R435  0  [SM-7351-RES-0402]
R436  0  [SM-7351-RES-0402]
R440  0  [SM-7351-RES-0402]
R450  0  [SM-7351-RES-0402]
R454  0  [SM-7351-RES-0402]
R476  4.99K  [SM-7351-RES-0402]
R497  22K  [SM-7351-RES-0402]
R500  33  [SM-7351-RES-0402]
R501  22K  [SM-7351-RES-0402]
R502  19.1K  [SM-7351-RES-0402]
R505  33  [SM-7351-RES-0402]
R506  19.1K  [SM-7351-RES-0402]
R509  22K  [SM-7351-RES-0402]
R510  19.1K  [SM-7351-RES-0402]
R511  49.9K  [SM-7351-RES-0402]
R518  22K  [SM-7351-RES-0402]
R523  22K  [SM-7351-RES-0402]
R524  22K  [SM-7351-RES-0402]
R525  19.1K  [SM-7351-RES-0402]
R539  22K  [SM-7351-RES-0402]
U11  AM437X_ZDN  [AM437X_ZDN]  (sections -1,-10,-11,-12,-13,-14,-15,-16,-17,-18,-19,-2,-20,-21,-22,-23,-24,-25,-3,-4,-5,-6,-7,-8,-9)
U18  OPA365  [SOT23-5]
U19  OPA365  [SOT23-5]
U22  OPA365  [SOT23-5]
U24  OPA365  [SOT23-5]
U28  LM4132  [sot23-5]
U56  REF3025  [SOT23-3-44M]
sheet Pg17: JTAG Debug
C41  0.01uF  [SM-7351-CAP-0402]
C127  0.01uF  [SM-7351-CAP-0402]
C174  0.1uF  [SM-7351-CAP-0402]
C186  1uF  [SM-7351-CAP-0402]
C190  0.01uF  [SM-7351-CAP-0402]
J7  CTI JTAG  [header10x2]
R23  100K  [SM-7351-RES-0402]
R24  100K  [SM-7351-RES-0402]
R25  100K  [SM-7351-RES-0402]
R26  100K  [SM-7351-RES-0402]
R27  100K  [SM-7351-RES-0402]
R28  100K  [SM-7351-RES-0402]
R29  100K  [SM-7351-RES-0402]
R30  100K  [SM-7351-RES-0402]
R35  100K  [SM-7351-RES-0402]
R36  100K  [SM-7351-RES-0402]
R37  100K  [SM-7351-RES-0402]
R38  100K  [SM-7351-RES-0402]
R39  100K  [SM-7351-RES-0402]
R40  100K  [SM-7351-RES-0402]
R41  100K  [SM-7351-RES-0402]
R42  100K  [SM-7351-RES-0402]
R47  100K  [SM-7351-RES-0402]
R48  100K  [SM-7351-RES-0402]
R49  100K  [SM-7351-RES-0402]
R300  10K  [SM-7351-RES-0402]
R314  10K  [SM-7351-RES-0402]
R315  10K  [SM-7351-RES-0402]
R316  10K  [SM-7351-RES-0402]
R317  10K  [SM-7351-RES-0402]
R318  10K  [SM-7351-RES-0402]
R319  10K  [SM-7351-RES-0402]
R320  10K  [SM-7351-RES-0402]
R321  10K  [SM-7351-RES-0402]
R328  10K  [SM-7351-RES-0402]
R329  10K  [SM-7351-RES-0402]
R330  10K  [SM-7351-RES-0402]
R331  10K  [SM-7351-RES-0402]
R332  10K  [SM-7351-RES-0402]
R333  10K  [SM-7351-RES-0402]
R334  10K  [SM-7351-RES-0402]
R335  10K  [SM-7351-RES-0402]
R340  10K  [SM-7351-RES-0402]
R341  10K  [SM-7351-RES-0402]
R342  10K  [SM-7351-RES-0402]
R389  100  [SM-7351-RES-0402]
R402  4.7K  [SM-7351-RES-0402]
R403  4.7K  [SM-7351-RES-0402]
R407  0  [SM-7351-RES-0402]
R413  0  [SM-7351-RES-0402]
R414  100  [SM-7351-RES-0402]
R426  10K  [SM-7351-RES-0402]
R429  0  [SM-7351-RES-0402]
R433  4.7K  [SM-7351-RES-0402]
TP4  TP1mm  [tp_smd1mmcircle]
TP5  TP1mm  [tp_smd1mmcircle]
TP6  TP1mm  [tp_smd1mmcircle]
U8  SN74LVC1G04  [SC70-5-43M]
U32  CAT24C256W  [SOIC_8]
sheet Pg18: USB JTAG
C61  0.01uF  [SM-7351-CAP-0402]
C73  0.01uF  [SM-7351-CAP-0402]
C76  0.01uF  [SM-7351-CAP-0402]
C78  0.1uF  [SM-7351-CAP-0402]
C169  0.01uF  [SM-7351-CAP-0402]
C170  0.01uF  [SM-7351-CAP-0402]
C196  0.01uF  [SM-7351-CAP-0402]
C209  0.01uF  [SM-7351-CAP-0402]
C225  0.01uF  [SM-7351-CAP-0402]
C226  0.01uF  [SM-7351-CAP-0402]
C227  0.01uF  [SM-7351-CAP-0402]
C228  2.2uF  [SM-7351-CAP-0805]
C235  0.01uF  [SM-7351-CAP-0402]
C239  0.01uF  [SM-7351-CAP-0402]
C245  4.7uF  [SM-7351-CAP-0603]
C246  0.01uF  [SM-7351-CAP-0402]
C249  0.01uF  [SM-7351-CAP-0402]
C250  0.01uF  [SM-7351-CAP-0402]
C251  4.7uF  [SM-7351-CAP-0603]
C255  18pF  [SM-7351-CAP-0402]
C258  4.7uF  [SM-7351-CAP-0603]
C259  0.01uF  [SM-7351-CAP-0402]
C260  0.01uF  [SM-7351-CAP-0402]
C261  18pF  [SM-7351-CAP-0402]
C264  0.01uF  [SM-7351-CAP-0402]
C265  0.01uF  [SM-7351-CAP-0402]
C274  0.01uF  [SM-7351-CAP-0402]
C275  0.01uF  [SM-7351-CAP-0402]
D12  Green LED  [sm_led_0805]
FB12  150OHM800mA  [sm-7351-ind-0805]
FB13  220OHM2A  [sm-7351-ind-0603]
FB15  220OHM2A  [sm-7351-ind-0603]
FB16  220OHM2A  [sm-7351-ind-0603]
J18  USB_MicroAB  [ZX62-AB-5PA]
R71  0  [SM-7351-RES-0402]
R72  0  [SM-7351-RES-0402]
R88  0  [SM-7351-RES-0402]
R89  0  [SM-7351-RES-0402]
R112  0  [SM-7351-RES-0402]
R113  0  [SM-7351-RES-0402]
R114  0  [SM-7351-RES-0402]
R115  0  [SM-7351-RES-0402]
R116  0  [SM-7351-RES-0402]
R117  0  [SM-7351-RES-0402]
R118  0  [SM-7351-RES-0402]
R119  0  [SM-7351-RES-0402]
R120  0  [SM-7351-RES-0402]
R133  0  [SM-7351-RES-0402]
R135  10K  [SM-7351-RES-0402]
R160  4.7K  [SM-7351-RES-0402]
R168  4.7K  [SM-7351-RES-0402]
R169  10K  [SM-7351-RES-0402]
R170  0  [SM-7351-RES-0402]
R171  220  [SM-7351-RES-0402]
R178  10K  [SM-7351-RES-0402]
R180  2.2K  [sm-7351-res-0402]
R376  0  [SM-7351-RES-0402]
R381  0  [SM-7351-RES-0402]
R421  0  [SM-7351-RES-0402]
R451  0  [SM-7351-RES-0603]
R460  12K, 1%  [SM-7351-RES-0402]
R489  0  [SM-7351-RES-0402]
TP10  TP1mm  [tp_smd1mmcircle]
U13  FT2232HL  [LQFP64pin]
U16  93LC56B  [SOIC_8]
U41  SN74AVC2T244  [son2x1-8-16m]
U45  SN74AVC4T245  [U_16_PW]
U47  TPD2E001  [U_5_DRL]
U49  SN74AVC2T244  [son2x1-8-16m]
U50  SN74LVC1G00DCK  [U_5_DCK]
U51  SN74LVC1G07  [SC70-5-43M]
Y4  12MHz  [SM_OSC_ABM3]
sheet Pg20: RTC
C243  15pF  [SM-7351-CAP-0402]
C248  15pF  [SM-7351-CAP-0402]
C263  0.01uF  [SM-7351-CAP-0402]
R143  0  [SM-7351-RES-0402]
R148  0  [SM-7351-RES-0402]
R163  0  [SM-7351-RES-0402]
R172  10K  [SM-7351-RES-0402]
R467  0  [SM-7351-RES-0402]
R479  10K  [SM-7351-RES-0402]
TP13  TP  [TH_TP_5002]
U48  SN74LVC1G07  [u_5_dck]
Y3  32.768KHz MC-306  [MC-306]

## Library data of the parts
M1-M8 = 2M_Screw_4-40_1_4
M9-M12 = 2M_Standoff4-40x1_4x5_8Alum
M13-M16 = 2M_RubberFeet_screwno4
PCB1 = 3K_AM437xIndustrialEVMBarePCB: Version: 1.3
C80 C102 = 1C_22uFCapacitor16V10%0805
C55 C57 C78 C103 C106 C107 C112 C125 C174 C306 C307 C311-C313 C317 C330 C338 = 1C_0.1uFCapacitor16V10%0402
C2 C104 C105 C113 C117 C123 C136 C335 C341 C342 = 1C_10uFCapacitor16V10%0805
C108 = 1C_10pFCapacitor50V1%smd0402
C54 C56 C109 C111 C300 C308 C321 C332 = 1C_0.001uFCapacitor50V5%0402
C13-C15 C20 C25 C41 C61 C73 C76 C89 C90 C92 C101 C119 C126 C127 C140 C145 C146 C156 C166 C169 C170 C190 C196 C209 C225-C227 C235 C238 C239 C246 C247 C249 C250 C259 C260 C263-C265 C274 C275 C277-C279 C282-C285 C288-C292 C294-C297 C299 C301 C302 C304 C314-C316 C318 C323 C324 C328 C329 = 1C_0.01uFCapacitor16V10%0402
R162 R507 R508 = 1R_49.9OhmResistor1_16W0402
R198 R504 = 1R_240OhmResistor1_16W0402
R199 R205 R206 R216-R221 R503 R516 R517 R520-R522 R527-R535 = 1R_47ohm1_16W1%smd0402
R225 = 1R_10ohm1_16W5%smd0402
R2 R3 R135 R169 R172 R178 R226 R297 R300 R305 R314-R321 R328-R335 R340-R343 R347 R426 R479 R549 = 1R_10KOhmResistor1_16W0402
R8 R10 R12 R71 R72 R88 R89 R103 R104 R109 R110 R112-R120 R124 R126 R129 R133 R143 R148 R163 R170 R202 R232 R275 R277 R279 R304 R309 R350 R376 R381 R407 R413 R421 R429 R435 R436 R440 R450 R454 R467 R484 R489 R494 = 1R_ZeroOhmResistor1_16W0402
R1 R7 R9 R11 R23-R30 R35-R42 R47-R49 R233 R274 R276 R278 = 1R_100KOhmResistor1_16W0402
R470 R474 = 1R_2.2KohmResistor1_8W1%0402
U20 U21 = 1A_MT41K256M16HA
U25 = TPS51200
Q1-Q8 = 1Q_MOSFET_NChan_BSS138
R4-R6 R268 R271 R272 = 1R_150ohm1_16W1%SMD0402
U1 U2 = 1F_LED_Tricolor_RedGreenYellow
A1 = 4P_CameraModuleOV2659_2Mp
C132 C133 = 1C_2.2uFCapacitor6.3V10%smd0603
C135 C243 C248 = 1C_15pFCapacitor50V10%smd0402
C151 C186 = 1C_1uFCapacitor10V10%0402
J5 = 2C_Conn_FPC_AXK_24pin
R13 R17 R303 R313 R326 R327 R451 = 1R_ZeroOhmResistor1_16W0603
R15 R16 R160 R168 R402 R403 R433 = 1R_4.7KOhmResistor1_16W0402
R301 = 1R_30.1Kohm1_16W1%smd0402
R306 = 1R_39Kohm1_16W5%smd0402
TP4-TP6 TP10 TP17 = 2H_Testpoint_SMD1mmCircle
U6 = 1A_SN74LVC8T245
U30 = 1A_TPS79301
U31 = 1A_TXS0102
U34 = 1A_SN74AVC1T45
U38 U45 = 1A_SN74AVC4T245
C68 = 1C_47nFCapacitor25V10%smd0402
C83 C84 C286 C309 C325 C333 C334 = 1C_180pF50V5%SMD0402
C85 C86 C91 C93 C298 C305 C310 C331 = 1C_100pFCapacitor25V10%0402
C120 C245 C251 C258 = 1C_4.7uFCapacitor16V10%0603
C293 = 1C_0.47uFCapacitor16V10%0402
J2 = 2H_Header_3x1
R58 R64 R68 = 1R_4.02KohmResistor1_16W1%0402
R154 = 95.3KOhmResistor1_16W0402
R185 R188 R189 R207 R497 R501 R509 R518 R523 R524 R539 = 1R_22Kohm1_16W1%SMD0402
R191 R192 R212 R511 = 1R_49.9KOhmResistor1_16W0402
R193 R195 R197 R200 R203 R209 R211 R222 = 1R_1KOhmResistor1_16W0402
R194 R196 R208 R210 = 1R_28.7Kohm1_16W1%smd0402
R201 R204 R223 R500 R505 = 1R_33ohmResistor1_16W5%0402
R476 = 1R_4.99KOhmResistor1_16W0402
R502 R506 R510 R525 = 1R_19.1Kohm1_16W1%smd0402
U11 = am437x_ZDN_Industrial_EVM
U18 U19 U22 U24 = 1A_OPA365
U28 = 1A_LM4132
U56 = 1A_REF3025
J7 = 2H_Header10x2_CJTAG
R389 R414 = 1R_100ohm1_16W1%SMD0402
U8 = 1A_SN74LVC1G04
U32 = 1A_CAT24C256W
C228 = 1C_2.2uF16V10%SMD0805
C255 C261 = 1C_18pFCapacitor16V10%0402
D12 = 1F_LED_Green
FB12 = 1L_FerBead_180ohm200mA
FB13 FB15 FB16 = 1L_FerriteBead_220ohm2A
J18 = 2C_MicroUSBAB
R171 = 1R_220ohm1_10W1%smd0402
R180 = 1R_2.2KOhmResistor1_16W0402
R460 = 1R_12Kohm1_16W1%SMD0402
U13 = 1A_FT2232_2
U16 = 1A_93C56EEPROM2Kbit
U41 U49 = 1A_SN74AVC2T244
U47 = 1A_TPD2E001DRL
U50 = 1A_SN74LVC1G00DCK
U48 U51 = 1A_SN74LVC1G07
Y4 = 1Y_Crystal12MHzABM3
TP13 = 2H_TestPointThroughHole
Y3 = 1Y_Crystal_SMD32_768kHz

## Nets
AGND: C2.2 C15.2 J5.1 R17.2(P2)
DGND: C13.2 C14.2 C20.2 C25.2 C41.2 C61.2 C68.2 C73.2 C76.2 C78.2 C80.2 C83.2 C84.2 C85.2 C86.2 C89.2 C90.2 C91.2 C92.2 C93.2 C101.2 C102.2 C103.2 C104.2 C105.2 C106.2 C107.2 C108.2 C109.2 C111.2 C112.2 C113.2 C117.2 C119.2 C120.2 C123.2 C125.2 C126.2 C127.2 C132.2 C133.2 C136.2 C140.2 C145.2 C146.2 C151.2 C156.2 C166.2 C169.2 C170.2 C174.2 C186.2 C190.2 C196.2 C209.2 C225.2 C226.2 C227.2 C228.2 C235.2 C238.2 C239.2 C245.1 C246.1 C249.2 C250.1 C251.1 C255.2 C258.2 C259.2 C260.1 C261.2 C263.2 C264.2 C265.2 C274.1 C275.1 C277.2 C278.2 C279.2 C282.2 C283.2 C284.2 C285.2 C286.2 C288.2 C289.2 C290.2 C291.2 C292.2 C293.2 C294.2 C295.2 C296.2 C297.2 C299.2 C301.2 C302.2 C304.2 C307.2 C309.2 C311.2 C312.2 C314.2 C315.2 C316.2 C318.2 C321.2 C323.2 C324.2 C325.2 C328.2 C329.2 C330.2 C333.2 C334.2 C335.2 C338.2 C341.2 C342.2 FB12.2 J5.5 J5.7 J7.8(GND) J7.12(GND) J7.16(GND) J7.20(GND) J18.5(GND) Q1.S(SOURCE) Q2.S(SOURCE) Q3.S(SOURCE) Q4.S(SOURCE) Q5.S(SOURCE) Q6.S(SOURCE) Q7.S(SOURCE) Q8.S(SOURCE) R1.1(P1) R7.1(P1) R9.1(P1) R11.1(P1) R17.1(P1) R112.1(P1) R160.1(P1) R162.1(P1) R169.1(P1) R172.1(P1) R185.1(P1) R191.1(P1) R192.1(P1) R197.2(P2) R198.1(P1) R202.1(P1) R212.1(P1) R274.1(P1) R276.1(P1) R278.1(P1) R301.1(P1) R304.1(P1) R314.1(P1) R315.1(P1) R316.1(P1) R317.1(P1) R318.1(P1) R319.1(P1) R320.1(P1) R321.1(P1) R328.1(P1) R329.1(P1) R330.1(P1) R331.1(P1) R332.1(P1) R333.1(P1) R334.1(P1) R335.1(P1) R340.1(P1) R341.1(P1) R342.1(P1) R429.1(P1) R433.1(P1) R460.2(P2) R474.2 R476.1(P1) R504.1(P1) R509.1(P1) R511.1(P1) R518.1(P1) R539.1(P1) R549.1(P1) U6.2(DIR) U6.11(GND) U6.12(GND) U6.13(GND) U8.3(GND) U13.1(GND.1) U13.5(GND.2) U13.10(AGND) U13.11(GND.3) U13.13(TEST) U13.15(GND.4) U13.25(GND.5) U13.35(GND.6) U13.47(GND.7) U13.51(GND.8) U16.5(VSS) U16.7(NC1) U18.2(V-) U19.2(V-) U20.A9(VSS) U20.B1(VSSQ) U20.B3(VSS) U20.B9(VSSQ) U20.D1(VSSQ) U20.D8(VSSQ) U20.E1(VSS) U20.E2(VSSQ) U20.E8(VSSQ) U20.F9(VSSQ) U20.G1(VSSQ) U20.G8(VSS) U20.G9(VSSQ) U20.J2(VSS) U20.J8(VSS) U20.M1(VSS) U20.M9(VSS) U20.P1(VSS) U20.P9(VSS) U20.T1(VSS) U20.T9(VSS) U21.A9(VSS) U21.B1(VSSQ) U21.B3(VSS) U21.B9(VSSQ) U21.D1(VSSQ) U21.D8(VSSQ) U21.E1(VSS) U21.E2(VSSQ) U21.E8(VSSQ) U21.F9(VSSQ) U21.G1(VSSQ) U21.G8(VSS) U21.G9(VSSQ) U21.J2(VSS) U21.J8(VSS) U21.M1(VSS) U21.M9(VSS) U21.P1(VSS) U21.P9(VSS) U21.T1(VSS) U21.T9(VSS) U22.2(V-) U24.2(V-) U25.4(PGND) U25.8(GND) U25.11(PWRPD) U28.2(GND) U30.2(GND) U31.2(GND) U32.1(A0) U32.2(A1) U32.3(A2) U32.4(VSS) U34.2(GND) U34.5(DIR) U38.3(2DIR) U38.8(GND) U38.9(GND) U38.14(2~{OE}) U38.15(1~{OE}) U41.5(GND) U45.8(GND) U45.9(GND) U47.4(GND) U48.3(GND) U49.5(GND) U50.3(GND) U51.3(GND) U56.3(GND) ; also on sheet 9 10 11 12 13 14 15 16 17 18 19 20
GND_OSC1: C243.2 C248.2 U11.AD4(VSS_RTC)
GNDA_ADC: C54.2 C55.2 C56.2 C57.2 J2.3 R58.1 R64.1 R68.1 R202.2(P2) U11.AD15(ADC1_VREFN) U11.AE14(ADC0_VREFN) ; also on sheet 9 12
GNDUSBJ: FB12.1 J18.S1 J18.S2 J18.S3 J18.S4
V1_5D: C247.1 R313.2(P2) R470.1 R494.2(P2) ; also on sheet 9 11
V1_8D: Q1.G(GATE) R1.2(P2) R309.2(P2) R479.2(P2) ; also on sheet 9 11 13
V1_8DADC: C119.1 C120.1 R110.1(P1) R126.1(P1) U28.5(VREF)
V1_8FTDI: C61.1 C73.1 C76.1 C239.1 C258.1 U13.12(VCORE.1) U13.37(VCORE.2) U13.49(VREGOUT) U13.64(VCORE.3)
V2_5MTR: R194.2(P2) R196.2(P2) R208.2(P2) R210.2(P2) U56.2(OUT)
V2_8A: C2.1 C15.1 J5.3 R13.2(P2)
V2_8D: C13.1 C25.1 C123.1 C140.1 C145.1 C146.1 J5.12 R13.1(P1) R15.2(P2) R16.2(P2) R303.1(P1) R305.2(P2) TP17.1 U6.23(VCCB) U6.24(VCCB) U31.3(VCCA) U34.6(VCCB) U38.16(VCCB)
V2_8D_EN: R309.1(P1) U30.3(EN)
V2_8D_FB: C135.2 R301.2(P2) R306.1(P1) U30.5(FB)
V2_8D_OUT: C132.1 C135.1 R303.2(P2) R306.2(P2) U30.6(OUT)
V3_3D: C20.1 C41.1 C113.1 C126.1 C127.1 C133.1 C156.1 C166.1 C169.1 C190.1 C196.1 C263.1 C264.1 C274.2 C275.2 J7.5(TVDD) R23.2(P2) R24.2(P2) R25.2(P2) R26.2(P2) R27.2(P2) R28.2(P2) R29.2(P2) R30.2(P2) R35.2(P2) R36.2(P2) R37.2(P2) R38.2(P2) R39.2(P2) R40.2(P2) R41.2(P2) R42.2(P2) R47.2(P2) R48.2(P2) R49.2(P2) R232.2(P2) R233.2(P2) R297.2(P2) R300.2(P2) R343.2(P2) R347.2(P2) R402.2(P2) R403.2(P2) R426.2(P2) R451.2(P2) U1.1(A) U2.1(A) U6.1(VCCA) U8.5(VCC) U25.10(VIN) U30.1(IN) U31.7(VCCB) U32.8(VCC) U34.1(VCCA) U38.1(VCCA) U38.2(1DIR) U41.8(VCCB) U45.16(VCCB) U48.5(VCC) U49.1(VCCA) U49.3(A2) U50.5(VCC) U51.5(VCC) ; also on sheet 9 10 11 12 13 14 15 16 17 18 19 20
V3_3FTDI: C78.1 C170.1 C209.1 C227.1 C228.1 C235.1 C249.1 C259.1 C260.2 C265.1 FB15.2 FB16.2 R135.2(P2) R178.2(P2) R451.1(P1) U13.20(VCCIO.1) U13.31(VCCIO.2) U13.42(VCCIO.3) U13.50(VREGIN) U13.56(VCCIO.4) U16.6(NC2) U16.8(VCC) U41.1(VCCA) U45.1(VCCA) U45.2(1DIR) U45.3(2DIR) U49.8(VCCB)
V3_3MTR: R201.2 R204.2 R223.2 R500.2 R505.2 ; also on sheet 10
V5_0D: C117.1 R2.2(P2) R3.2(P2) U28.4(VIN) ; also on sheet 11 12 17 20
V24_0MTR: R154.2(P2) ; also on sheet 10 20
VDDR_VREF: C112.1 C307.1 C311.1 C312.1 C313.2 C317.2 C330.1 U20.H1(VREFDQ) U20.M8(VREFCA) U21.H1(VREFDQ) U21.M8(VREFCA) U25.6(REFOUT)
VDDR_VTT: C103.1 C104.1 C106.1 C335.1 C338.1 C342.1 R199.1(P1) R205.1(P1) R206.1(P1) R216.1(P1) R217.1(P1) R218.1(P1) R219.1(P1) R220.1(P1) R221.1(P1) R225.2(P2) R503.1(P1) R516.1(P1) R517.1(P1) R520.1(P1) R521.1(P1) R522.1(P1) R527.1(P1) R528.1(P1) R529.1(P1) R530.1(P1) R531.1(P1) R532.1(P1) R533.1(P1) R534.1(P1) R535.1(P1) U25.3(VO)
VDDS_DDR: C80.1 C102.1 C105.1 C107.1 C111.1 C277.1 C278.1 C279.1 C282.1 C283.1 C284.1 C285.1 C288.1 C289.1 C290.1 C291.1 C292.1 C294.1 C295.1 C296.1 C297.1 C299.1 C301.1 C302.1 C304.1 C306.2 C313.1 C314.1 C315.1 C316.1 C317.1 C318.1 C323.1 C324.1 C328.1 C329.1 C341.1 R226.2(P2) R494.1(P1) U20.A1(VDDQ) U20.A8(VDDQ) U20.B2(VDD) U20.C1(VDDQ) U20.C9(VDDQ) U20.D2(VDDQ) U20.D9(VDD) U20.E9(VDDQ) U20.F1(VDDQ) U20.G7(VDD) U20.H2(VDDQ) U20.H9(VDDQ) U20.K2(VDD) U20.K8(VDD) U20.N1(VDD) U20.N9(VDD) U20.R1(VDD) U20.R9(VDD) U21.A1(VDDQ) U21.A8(VDDQ) U21.B2(VDD) U21.C1(VDDQ) U21.C9(VDDQ) U21.D2(VDDQ) U21.D9(VDD) U21.E9(VDDQ) U21.F1(VDDQ) U21.G7(VDD) U21.H2(VDDQ) U21.H9(VDDQ) U21.K2(VDD) U21.K8(VDD) U21.N1(VDD) U21.N9(VDD) U21.R1(VDD) U21.R9(VDD) U25.2(VLDOIN)
ADC0_VREFP: C56.1 C57.1 R126.2(P2) U11.AD14(ADC0_VREFP)
ADC1_VREFP: C54.1 C55.1 R110.2(P2) U11.AE15(ADC1_VREFP)
AM437X_AIN0: R450.1(P1) ; also on sheet 12
AM437X_AIN1: R440.1(P1) ; also on sheet 12
AM437X_AIN2: R435.1(P1) ; also on sheet 12
AM437X_AIN3: R436.1(P1) ; also on sheet 12
AM437X_AIN4: R104.1(P1) ; also on sheet 12
AM437X_AIN5: R103.1(P1) ; also on sheet 12
AM437X_AIN6: R129.1(P1) ; also on sheet 12
AM437X_AIN7: R124.1(P1) ; also on sheet 12
AM437X_CAM0_DATA0: R326.2(P2) U11.AE18(CAM0_DATA0) ; also on sheet 17
AM437X_CAM0_DATA1: R327.2(P2) ; also on sheet 10 17
AM437X_CAM0_DATA2: U6.5(A3) U11.Y18(CAM0_DATA2)
AM437X_CAM0_DATA3: U6.6(A4) U11.AA18(CAM0_DATA3)
AM437X_CAM0_DATA4: U6.7(A5) ; also on sheet 10
AM437X_CAM0_DATA5: U6.8(A6) ; also on sheet 10
AM437X_CAM0_DATA6: U6.9(A7) U11.AE20(CAM0_DATA6) ; also on sheet 17
AM437X_CAM0_DATA7: U6.10(A8) U11.AD20(CAM0_DATA7)
AM437X_CAM0_HSYNC: U11.AE17(CAM0_HSYNC) U38.7(2A2)
AM437X_CAM0_PCLK: U11.AC20(CAM0_PCLK) U34.3(A)
AM437X_CAM0_VSYNC: U11.AD18(CAM0_VSYNC) U38.6(2A1)
AM437X_CAM1_DATA2: R277.1(P1) ; also on sheet 17
AM437X_CAM1_WEN: R275.1(P1) ; also on sheet 17
AM437x_GPIO_CAM: R350.2(P2) U11.AD17(CAM0_WEN/GPIO)
AM437X_LCD_AC_BIAS_EN: R8.1(P1) R49.1(P1) R341.2(P2) ; also on sheet 17
AM437X_LCD_HSYNC: R48.1(P1) R279.2(P2) R342.2(P2) ; also on sheet 17
AM437X_LCD_PCLK: R10.2(P2) ; also on sheet 17
AM437X_LCD_VSYNC: R12.1(P1) R47.1(P1) R340.2(P2) ; also on sheet 17
AM437X_UART0_CTSn: R72.1(P1) U11.L25(UART0_CTSn)
AM437X_UART0_RTSn: R71.1(P1) U11.J25(UART0_RTSn)
AM437X_UART0_RXD: R89.1(P1) U11.K25(UART0_RXD)
AM437X_UART0_TXD: R88.1(P1) U11.J24(UART0_TXD) ; also on sheet 17
CAM0_GIO0: C151.1 R347.1(P1) R350.1(P1) U38.5(1A2)
CAM_MTR_EN: R343.1(P1) U6.22(~{OE}) ; also on sheet 17
CAM_SRCCLK: U11.C24(XDMA_EVENT_INTR1/CLKOUT2) U38.4(1A1)
DDR_A0: R528.2(P2) U11.N1(DDR_A0) U20.N3(A0) U21.N3(A0)
DDR_A1: R218.2(P2) U11.L1(DDR_A1) U20.P7(A1) U21.P7(A1)
DDR_A2: R530.2(P2) U11.L2(DDR_A2) U20.P3(A2) U21.P3(A2)
DDR_A3: R535.2(P2) U11.P2(DDR_A3) U20.N2(A3) U21.N2(A3)
DDR_A4: R520.2(P2) U11.P1(DDR_A4) U20.P8(A4) U21.P8(A4)
DDR_A5: R533.2(P2) U11.R5(DDR_A5) U20.P2(A5) U21.P2(A5)
DDR_A6: R516.2(P2) U11.R4(DDR_A6) U20.R8(A6) U21.R8(A6)
DDR_A7: R534.2(P2) U11.R3(DDR_A7) U20.R2(A7) U21.R2(A7)
DDR_A8: R221.2(P2) U11.R2(DDR_A8) U20.T8(A8) U21.T8(A8)
DDR_A9: R217.2(P2) U11.R1(DDR_A9) U20.R3(A9) U21.R3(A9)
DDR_A10: R205.2(P2) U11.M6(DDR_A10) U20.L7(A10/AP) U21.L7(A10/AP)
DDR_A11: R219.2(P2) U11.T5(DDR_A11) U20.R7(A11) U21.R7(A11)
DDR_A12: R527.2(P2) U11.T4(DDR_A12) U20.N7(A12/~{BC}) U21.N7(A12/~{BC})
DDR_A13: R216.2(P2) U11.N5(DDR_A13) U20.T3(A13) U21.T3(A13)
DDR_A14: R220.2(P2) U11.T3(DDR_A14) U20.T7(A14) U21.T7(A14)
DDR_BA0: R522.2(P2) U11.K1(DDR_BA0) U20.M2(BA0) U21.M2(BA0)
DDR_BA1: R206.2(P2) U11.K2(DDR_BA1) U20.N8(BA1) U21.N8(BA1)
DDR_BA2: R531.2(P2) U11.K3(DDR_BA2) U20.M3(BA2) U21.M3(BA2)
DDR_CASN: R532.2(P2) U11.N3(DDR_CASn) U20.K3(CASn) U21.K3(CASn)
DDR_CKE: R199.2(P2) R484.1(P1) U20.K9(CKE) U21.K9(CKE)
DDR_CKE0: R484.2(P2) U11.M3(DDR_CKE0)
DDR_CLK: R507.2(P2) U11.M2(DDR_CK) U20.J7(CK) U21.J7(CK)
DDR_CLKn: R508.2(P2) U11.M1(DDR_CKn) U20.K7(CKn) U21.K7(CKn)
DDR_CS0n: R521.2(P2) U11.M5(DDR_CSN0) U20.L2(CSn) U21.L2(CSn)
DDR_D0: U11.E3(DDR_D0) U20.E3(DQ0)
DDR_D1: U11.E2(DDR_D1) U20.F7(DQ1)
DDR_D2: U11.E1(DDR_D2) U20.F2(DQ2)
DDR_D3: U11.F3(DDR_D3) U20.F8(DQ3)
DDR_D4: U11.G4(DDR_D4) U20.H3(DQ4)
DDR_D5: U11.G3(DDR_D5) U20.H8(DQ5)
DDR_D6: U11.G2(DDR_D6) U20.G2(DQ6)
DDR_D7: U11.G1(DDR_D7) U20.H7(DQ7)
DDR_D8: U11.H1(DDR_D8) U20.D7(DQ8)
DDR_D9: U11.J6(DDR_D9) U20.C3(DQ9)
DDR_D10: U11.J5(DDR_D10) U20.C8(DQ10)
DDR_D11: U11.J4(DDR_D11) U20.C2(DQ11)
DDR_D12: U11.J3(DDR_D12) U20.A7(DQ12)
DDR_D13: U11.K6(DDR_D13) U20.A2(DQ13)
DDR_D14: U11.K5(DDR_D14) U20.B8(DQ14)
DDR_D15: U11.K4(DDR_D15) U20.A3(DQ15)
DDR_D16: U11.V5(DDR_D16) U21.E3(DQ0)
DDR_D17: U11.V4(DDR_D17) U21.F7(DQ1)
DDR_D18: U11.V3(DDR_D18) U21.F2(DQ2)
DDR_D19: U11.V2(DDR_D19) U21.F8(DQ3)
DDR_D20: U11.V1(DDR_D20) U21.H3(DQ4)
DDR_D21: U11.W4(DDR_D21) U21.H8(DQ5)
DDR_D22: U11.W5(DDR_D22) U21.G2(DQ6)
DDR_D23: U11.W6(DDR_D23) U21.H7(DQ7)
DDR_D24: U11.Y2(DDR_D24) U21.D7(DQ8)
DDR_D25: U11.Y3(DDR_D25) U21.C3(DQ9)
DDR_D26: U11.Y4(DDR_D26) U21.C8(DQ10)
DDR_D27: U11.AA3(DDR_D27) U21.C2(DQ11)
DDR_D28: U11.AB2(DDR_D28) U21.A7(DQ12)
DDR_D29: U11.AB1(DDR_D29) U21.A2(DQ13)
DDR_D30: U11.AC1(DDR_D30) U21.B8(DQ14)
DDR_D31: U11.AC2(DDR_D31) U21.A3(DQ15)
DDR_DQM0: U11.F4(DDR_DQM0) U20.E7(LDM)
DDR_DQM1: U11.H2(DDR_DQM1) U20.D3(UDM)
DDR_DQM2: U11.V6(DDR_DQM2) U21.E7(LDM)
DDR_DQM3: U11.Y1(DDR_DQM3) U21.D3(UDM)
DDR_DQS0: U11.F2(DDR_DQS0) U20.F3(LDQS)
DDR_DQS1: U11.J2(DDR_DQS1) U20.C7(UDQS)
DDR_DQS2: U11.W1(DDR_DQS2) U21.F3(LDQS)
DDR_DQS3: U11.AA1(DDR_DQS3) U21.C7(UDQS)
DDR_DQSN0: U11.F1(DDR_DQS0n) U20.G3(LDQSn)
DDR_DQSN1: U11.J1(DDR_DQS1n) U20.B7(UDQSn)
DDR_DQSN2: U11.W2(DDR_DQS2n) U21.G3(LDQSn)
DDR_DQSN3: U11.AA2(DDR_DQS3n) U21.B7(UDQSn)
DDR_ODT: R517.2(P2) U11.U1(DDR_ODT0) U20.K1(ODT) U21.K1(ODT)
DDR_RASN: R503.2(P2) U11.N2(DDR_RASn) U20.J3(RASn) U21.J3(RASn)
DDR_RESETn: U11.T1(DDR_RESETn) U20.T2(RESETn) U21.T2(RESETn)
DDR_WEn: R529.2(P2) U11.N4(DDR_WEn) U20.L3(WEn) U21.L3(WEn)
EECS: U13.63(EECS) U16.1(CS)
EEDATA: R180.1(P1) U13.61(EEDATA) U16.3(DI)
EESK: U13.62(EESK) U16.2(CLK)
EMU2: J7.17(EMU2) TP4.1
EMU3: J7.18(EMU3) TP6.1
EMU4: J7.19(EMU4) TP5.1
EMU_RSTn: C174.1 J7.15(SRST) R389.1(P1)
EMU_USB_DM: J18.2(DM) U13.7(DM) U47.5(IO2)
EMU_USB_DP: J18.3(DP) U13.8(DP) U47.3(IO1)
F_ADBUS0: R133.2(P2) U13.16(ADBUS0)
F_ADBUS1: R120.2(P2) U13.17(ADBUS1)
F_ADBUS2: R119.2(P2) U13.18(ADBUS2)
F_ADBUS3: R118.2(P2) U13.19(ADBUS3)
F_ADBUS4: R117.2(P2) U13.21(ADBUS4)
F_ADBUS5: R115.2(P2) U13.26(ACBUS0)
F_ADBUS6: R116.2(P2) U13.23(ADBUS6)
F_ADBUS7: R113.2(P2) U13.30(ACBUS4)
FT_SRESET: R115.1(P1) R160.2(P2) U50.1(A)
FT_SRESETB: R489.2(P2) U51.4(Y)
FT_SRESETn: U50.4(Y) U51.2(A)
FT_VBUS: R170.1(P1) U50.2(B)
FTDI_REF: R460.1(P1) U13.6(REF)
FTDI_VPHY: C250.2 C251.2 FB16.1 U13.4(VPHY)
FTDI_VPLL: C245.2 C246.2 FB15.1 U13.9(VPLL)
GP_I2C_SCL: U31.8(B1) U32.6(SCL) ; also on sheet 11 13
GP_I2C_SDA: U31.1(B2) U32.5(SDA) ; also on sheet 11 13
IDC_SENSE: C325.1 R109.1(P1) R207.1(P1) R518.2(P2)
IS_IHB1: C309.1 R440.2(P2) R501.1(P1) R509.2(P2) U11.Y12(ADC0_AIN1)
IS_IHB2: C84.1 R185.2(P2) R189.1(P1) R436.2(P2) U11.AA13(ADC0_AIN3)
IS_IHB3: C333.1 R103.2(P2) R523.1(P1) R539.2(P2) U11.AC13(ADC0_AIN5)
IS_MIHB1: C286.1 R497.1(P1) U11.Y15(ADC1_AIN5)
IS_MIHB2: C83.1 R188.1(P1) U11.AB16(ADC1_AIN1)
IS_MIHB3: C334.1 R524.1(P1) U11.AB15(ADC1_AIN3)
JTAG_EMU0: J7.13(EMU0) R376.1(P1) R402.1(P1) U11.N23(JTAG_EMU0)
JTAG_EMU1: J7.14(EMU1) R381.1(P1) R403.1(P1) U11.T24(JTAG_EMU1)
JTAG_TCK: R407.2(P2) R413.2(P2) U11.AA25(JTAG_TCK) U45.13(1B1)
JTAG_TDI: J7.3(TDI) U11.Y20(JTAG_TDI) U45.12(1B2)
JTAG_TDO: J7.7(TDO) U11.AA24(JTAG_TDO) U49.2(A1)
JTAG_TMS: J7.1(TMS) U11.Y24(JTAG_TMS) U45.11(2B1)
JTAG_TRSTn: J7.2(TRSTn) R433.2(P2) U11.Y25(JTAG_TRSTn) U45.10(2B2)
JTAGPOD_DET: R421.1(P1) U8.4(Y)
MOT1_ADC: R435.2(P2) U11.Y13(ADC0_AIN2) ; also on sheet 10
MOT2_ADC: R129.2(P2) U11.AD13(ADC0_AIN6) ; also on sheet 10
MOT3_ADC: R124.2(P2) U11.AE13(ADC0_AIN7) ; also on sheet 10
MOT_PGND1: C308.1 R195.2(P2) ; also on sheet 10
MOT_PGND2: C300.1 R193.2(P2) ; also on sheet 10
MOT_PGND3: C332.1 R211.2(P2) ; also on sheet 10
MOT_PGNDTOTAL: C300.2 C308.2 C321.1 C332.2 R200.2(P2) R203.2(P2) R209.2(P2) R222.2(P2) ; also on sheet 10
MOTVM_ADC: C68.1 R154.1(P1) R454.1(P1) R476.2(P2)
PORZn: U48.2(A) ; also on sheet 15 18
PR1_EDC_SYNC0_OUT: R72.2(P2) ; also on sheet 17
PR1_EDC_SYNC1_OUT: R71.2(P2) ; also on sheet 17
RTCK: J7.9(TCKRTN) R413.1(P1)
SENSOR_HREF: J5.8 U38.10(2B2)
SENSOR_PCLK: J5.13 U34.4(B)
SENSOR_PWRDN: J5.11 R304.2(P2) R305.1(P1)
SENSOR_RESET: J5.15 U38.12(1B2)
SENSOR_SIO_C: J5.4 R15.1(P1) U31.5(A1)
SENSOR_SIO_D: J5.2 R16.1(P1) U31.4(A2)
SENSOR_VSYNC: J5.6 U38.11(2B1)
SENSOR_XCLK: J5.10 U38.13(1B1)
SENSOR_Y2: J5.24 U6.21(B1)
SENSOR_Y3: J5.23 U6.20(B2)
SENSOR_Y4: J5.22 U6.19(B3)
SENSOR_Y5: J5.21 U6.18(B4)
SENSOR_Y6: J5.20 U6.17(B5)
SENSOR_Y7: J5.19 U6.16(B6)
SENSOR_Y8: J5.18 U6.15(B7)
SENSOR_Y9: J5.17 U6.14(B8)
SYS_RESETn: R389.2(P2) ; also on sheet 13 14 15 17 18 19
SYS_WARMRESETn: R489.1(P1) ; also on sheet 18
SYSBOOT0: R26.1(P1) R318.2(P2) ; also on sheet 15
SYSBOOT1: R25.1(P1) R319.2(P2) ; also on sheet 15
SYSBOOT2: R24.1(P1) R320.2(P2) ; also on sheet 15
SYSBOOT3: R23.1(P1) R321.2(P2) ; also on sheet 15
SYSBOOT4: R30.1(P1) R314.2(P2) ; also on sheet 15
SYSBOOT5: R29.1(P1) R315.2(P2) ; also on sheet 15
SYSBOOT6: R28.1(P1) R316.2(P2) ; also on sheet 15
SYSBOOT7: R27.1(P1) R317.2(P2) ; also on sheet 15
SYSBOOT8: R39.1(P1) R331.2(P2) ; also on sheet 15
SYSBOOT9: R40.1(P1) R330.2(P2) ; also on sheet 15
SYSBOOT10: R41.1(P1) R329.2(P2) ; also on sheet 15
SYSBOOT11: R42.1(P1) R328.2(P2) ; also on sheet 15
SYSBOOT12: R35.1(P1) R335.2(P2) ; also on sheet 15
SYSBOOT13: R36.1(P1) R334.2(P2) ; also on sheet 15
SYSBOOT14: R37.1(P1) R333.2(P2) ; also on sheet 15
SYSBOOT15: R38.1(P1) R332.2(P2) ; also on sheet 15
TCK: J7.11(TCK) R407.1(P1)
UARTx_RXD: R89.2(P2) U13.38(BDBUS0)
UARTx_TXD: R88.2(P2) U13.39(BDBUS1)
USBJTAG_ENn: R421.2(P2) U41.4(~{OE}) U45.14(2~{OE}) U45.15(1~{OE}) U49.4(~{OE})
VAM437x_DDR_VREF: C238.1 C247.2 R470.2 R474.1 U11.T6(DDR_VREF)
VUSB_FTDI: C225.1 D12.2(Anode) FB13.2 R168.2(P2)
VUSB_JTAG: C226.1 FB13.1 J18.1(VBUS) U47.1(VCC)
XTIN: C261.1 U13.2(XTIN) Y4.1
XTOUT: C255.1 U13.3(XTOUT) Y4.2
N11217419: C306.1 R507.1(P1) R508.1(P1)
N11219802: R232.1(P1) U25.7(EN)
N11219922: R233.1(P1) U25.9(PGOOD)
N11219986: C108.1 R225.1(P1) U25.5(VOSNS)
N11220684: C109.1 R226.1(P1) R549.2(P2) U25.1(REFIN)
N12595082: R162.2(P2) U11.AC3(DDR_VTP)
N12745256: Q8.G(GATE) R9.2(P2) R10.1(P1)
N12745282: Q8.D(DRAIN) R272.1(P1)
N12745290: R272.2(P2) U1.2(R)
N12745520: Q6.G(GATE) R7.2(P2) R8.2(P2)
N12745536: Q6.D(DRAIN) R268.1(P1)
N12745804: Q7.G(GATE) R11.2(P2) R12.2(P2)
N12745812: R271.2(P2) U1.4(Y)
N12745820: Q7.D(DRAIN) R271.1(P1)
N12957779: R114.2(P2) U13.28(ACBUS2)
N12957783: R114.1(P1) U49.6(B2)
N12957791: R112.2(P2) U13.32(ACBUS5)
N12957851: R168.1(P1) R169.2(P2) R170.2(P2) U13.59(BCBUS7)
N12957949: R113.1(P1) U41.3(A2)
N12958009: R135.1(P1) U13.14(RESET#)
N12958129: D12.1(Cathode) R171.2
N12958219: R178.1(P1) R180.2(P2) U16.4(DO)
N12958339: TP10.1 U13.36(SUSPEND#)
N12958347: R171.1 U13.60(PWREN#)
N12958931: R116.1(P1) U41.2(A1)
N12958935: R117.1(P1) U45.7(2A2)
N12958939: R118.1(P1) U45.6(2A1)
N14606304: R504.2(P2) U20.L8(ZQ)
N14617357: R198.2(P2) U21.L8(ZQ)
N15803440: R172.2(P2) U11.AE2(ENZ_KALDO_1P8V)
N15803446: R143.2(P2) U11.AD6(PMIC_POWER_EN0)
N15803450: R467.1(P1) U11.AE4(OSC1_OUT)
N15803452: C248.1 R467.2(P2) Y3.4
N15803458: C243.1 U11.AE5(OSC1_IN) Y3.1
N15803478: R148.2(P2) U11.AE6(RTC_PORZ)
N15803480: R163.2(P2) U11.AE3(EXT_WAKEUP0)
N15803482: R148.1(P1) R479.1(P1) U48.4(Y)
N15803502: R163.1(P1) TP13.1
N15838226: C14.1 C136.1 J5.9 R313.1(P1)
N15840029: C125.1 U30.4(NR)
N15840733: R297.1(P1) U31.6(OE)
N16094628: J7.4(TDIS) R429.2(P2)
N16702915: R326.1(P1) U6.3(A1)
N16702921: R327.1(P1) U6.4(A2)
N17084990: R268.2(P2) U1.3(G)
N17085264: Q3.G(GATE) R278.2(P2) R279.1(P1)
N17085270: Q3.D(DRAIN) R5.1(P1)
N17085272: R5.2(P2) U2.2(R)
N17085280: Q5.G(GATE) R274.2(P2) R275.2(P2)
N17085284: Q5.D(DRAIN) R4.1(P1)
N17085292: Q4.G(GATE) R276.2(P2) R277.2(P2)
N17085296: R6.2(P2) U2.4(Y)
N17085298: Q4.D(DRAIN) R6.1(P1)
N17085459: R4.2(P2) U2.3(G)
N17197007: J7.10(GND) R414.2(P2)
N17197255: C186.1 R414.1(P1) R426.1(P1) U8.2(A)
N17205778: C89.1 R505.1 U22.5(V+)
N17205782: C310.2 R207.2(P2) R510.1(P1) U22.1(VOUT)
N17205788: C310.1 R197.1(P1) R510.2(P2) U22.4(IN-)
N17205791: C91.1 R208.1(P1) R209.1(P1) R511.2(P2) U22.3(IN+)
N17205925: R104.2(P2) R109.2(P2) U11.AB13(ADC0_AIN4)
N17205949: R450.2(P2) R454.2(P2) U11.AA12(ADC0_AIN0)
N17209063: C92.1 R204.1 U19.5(V+)
N17209071: C298.2 R497.2(P2) R501.2(P2) R502.1(P1) U19.1(VOUT)
N17209083: C298.1 R203.1(P1) R502.2(P2) U19.4(IN-)
N17209089: C85.1 R191.2(P2) R195.1(P1) R196.1(P1) U19.3(IN+)
N17209568: C90.1 R201.1 U18.5(V+)
N17209576: C305.2 R188.2(P2) R189.2(P2) R506.1(P1) U18.1(VOUT)
N17209588: C305.1 R200.1(P1) R506.2(P2) U18.4(IN-)
N17209594: C86.1 R192.2(P2) R193.1(P1) R194.1(P1) U18.3(IN+)
N17210087: C101.1 R223.1 U24.5(V+)
N17210095: C331.2 R523.2(P2) R524.2(P2) R525.1(P1) U24.1(VOUT)
N17210107: C331.1 R222.1(P1) R525.2(P2) U24.4(IN-)
N17210113: C93.1 R210.1(P1) R211.1(P1) R212.2(P2) U24.3(IN+)
N17757813: R133.1(P1) U45.4(1A1)
N17757815: R120.1(P1) U45.5(1A2)
N17758292: R119.1(P1) U49.7(B1)
N17758583: R376.2(P2) U41.7(B1)
N17758585: R381.2(P2) U41.6(B2)
N17814979: C293.1 R500.1 U56.1(IN)
N18074781: R64.2 U11.AA16(ADC1_AIN2)
N18074818: J2.1 U11.AE16(ADC1_AIN6)
N18074820: J2.2 U11.AD16(ADC1_AIN7)
N18139095: R300.1(P1) U32.7(WP)
N18365828: Q1.D(DRAIN) Q2.G(GATE) R2.1(P1)
N18365970: Q2.D(DRAIN) R3.1(P1) U28.3(EN)
N18405849: R68.2 U11.AC16(ADC1_AIN0)
N18405956: R58.2 U11.AA15(ADC1_AIN4)

Not connected (* = marked no-connect by the designer): J5 14* 16*; J7 6(NC)*; J18 4(ID)*; R143 1(P1)*; U8 1(NC)*; U11 M4(DDR_CSN1) N6(DDR_CKE1) T2(DDR_A15) U2(DDR_ODT1); U13 22(ADBUS5)* 24(ADBUS7)* 27(ACBUS1)* 29(ACBUS3)* 33(ACBUS6)* 34(ACBUS7)* 40(BDBUS2)* 41(BDBUS3)* 43(BDBUS4)* 44(BDBUS5)* 45(BDBUS6)* 46(BDBUS7)* 48(BCBUS0)* 52(BCBUS1)* 53(BCBUS2)* 54(BCBUS3)* 55(BCBUS4)* 57(BCBUS5)* 58(BCBUS6)*; U20 J1(NU0) J9(NU1) L1(NU2) L9(NU3) M7(NU4); U21 J1(NU0)* J9(NU1)* L1(NU2)* L9(NU3)* M7(NU4)*; U28 1(NC)*; U47 2(NC)*; U48 1(NC)*; U51 1(NC)*; Y3 2* 3*

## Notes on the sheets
sheet 1
- 1.8V Motor ADC Reference
- Motor Winding #1
- 2.5V Motor Reference
- Motor Winding #2
- Motor Winding #3
sheet 3
- LED0
- LED1
sheet 5
- USB JTAG
sheet 6
- ID Memory
- JTAG Pod Connector
- Boot Configuration
sheet 7
- ARM MPU AM437X Industrial EVM
  ZDN Package
- -See the Hardware User Guide for board details
- -See the Errata Document for design Issues
- -See the PCB Build Specification for PCB Details
